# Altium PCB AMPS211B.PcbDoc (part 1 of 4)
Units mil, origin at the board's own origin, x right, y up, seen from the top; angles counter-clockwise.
Board outline 3600 x 2600 mil, 4 copper layers (Top Layer, GND, Power, Bottom Layer), stack 61.6 mil thick; 202 components, 101 nets, 561 pads, 317 vias.
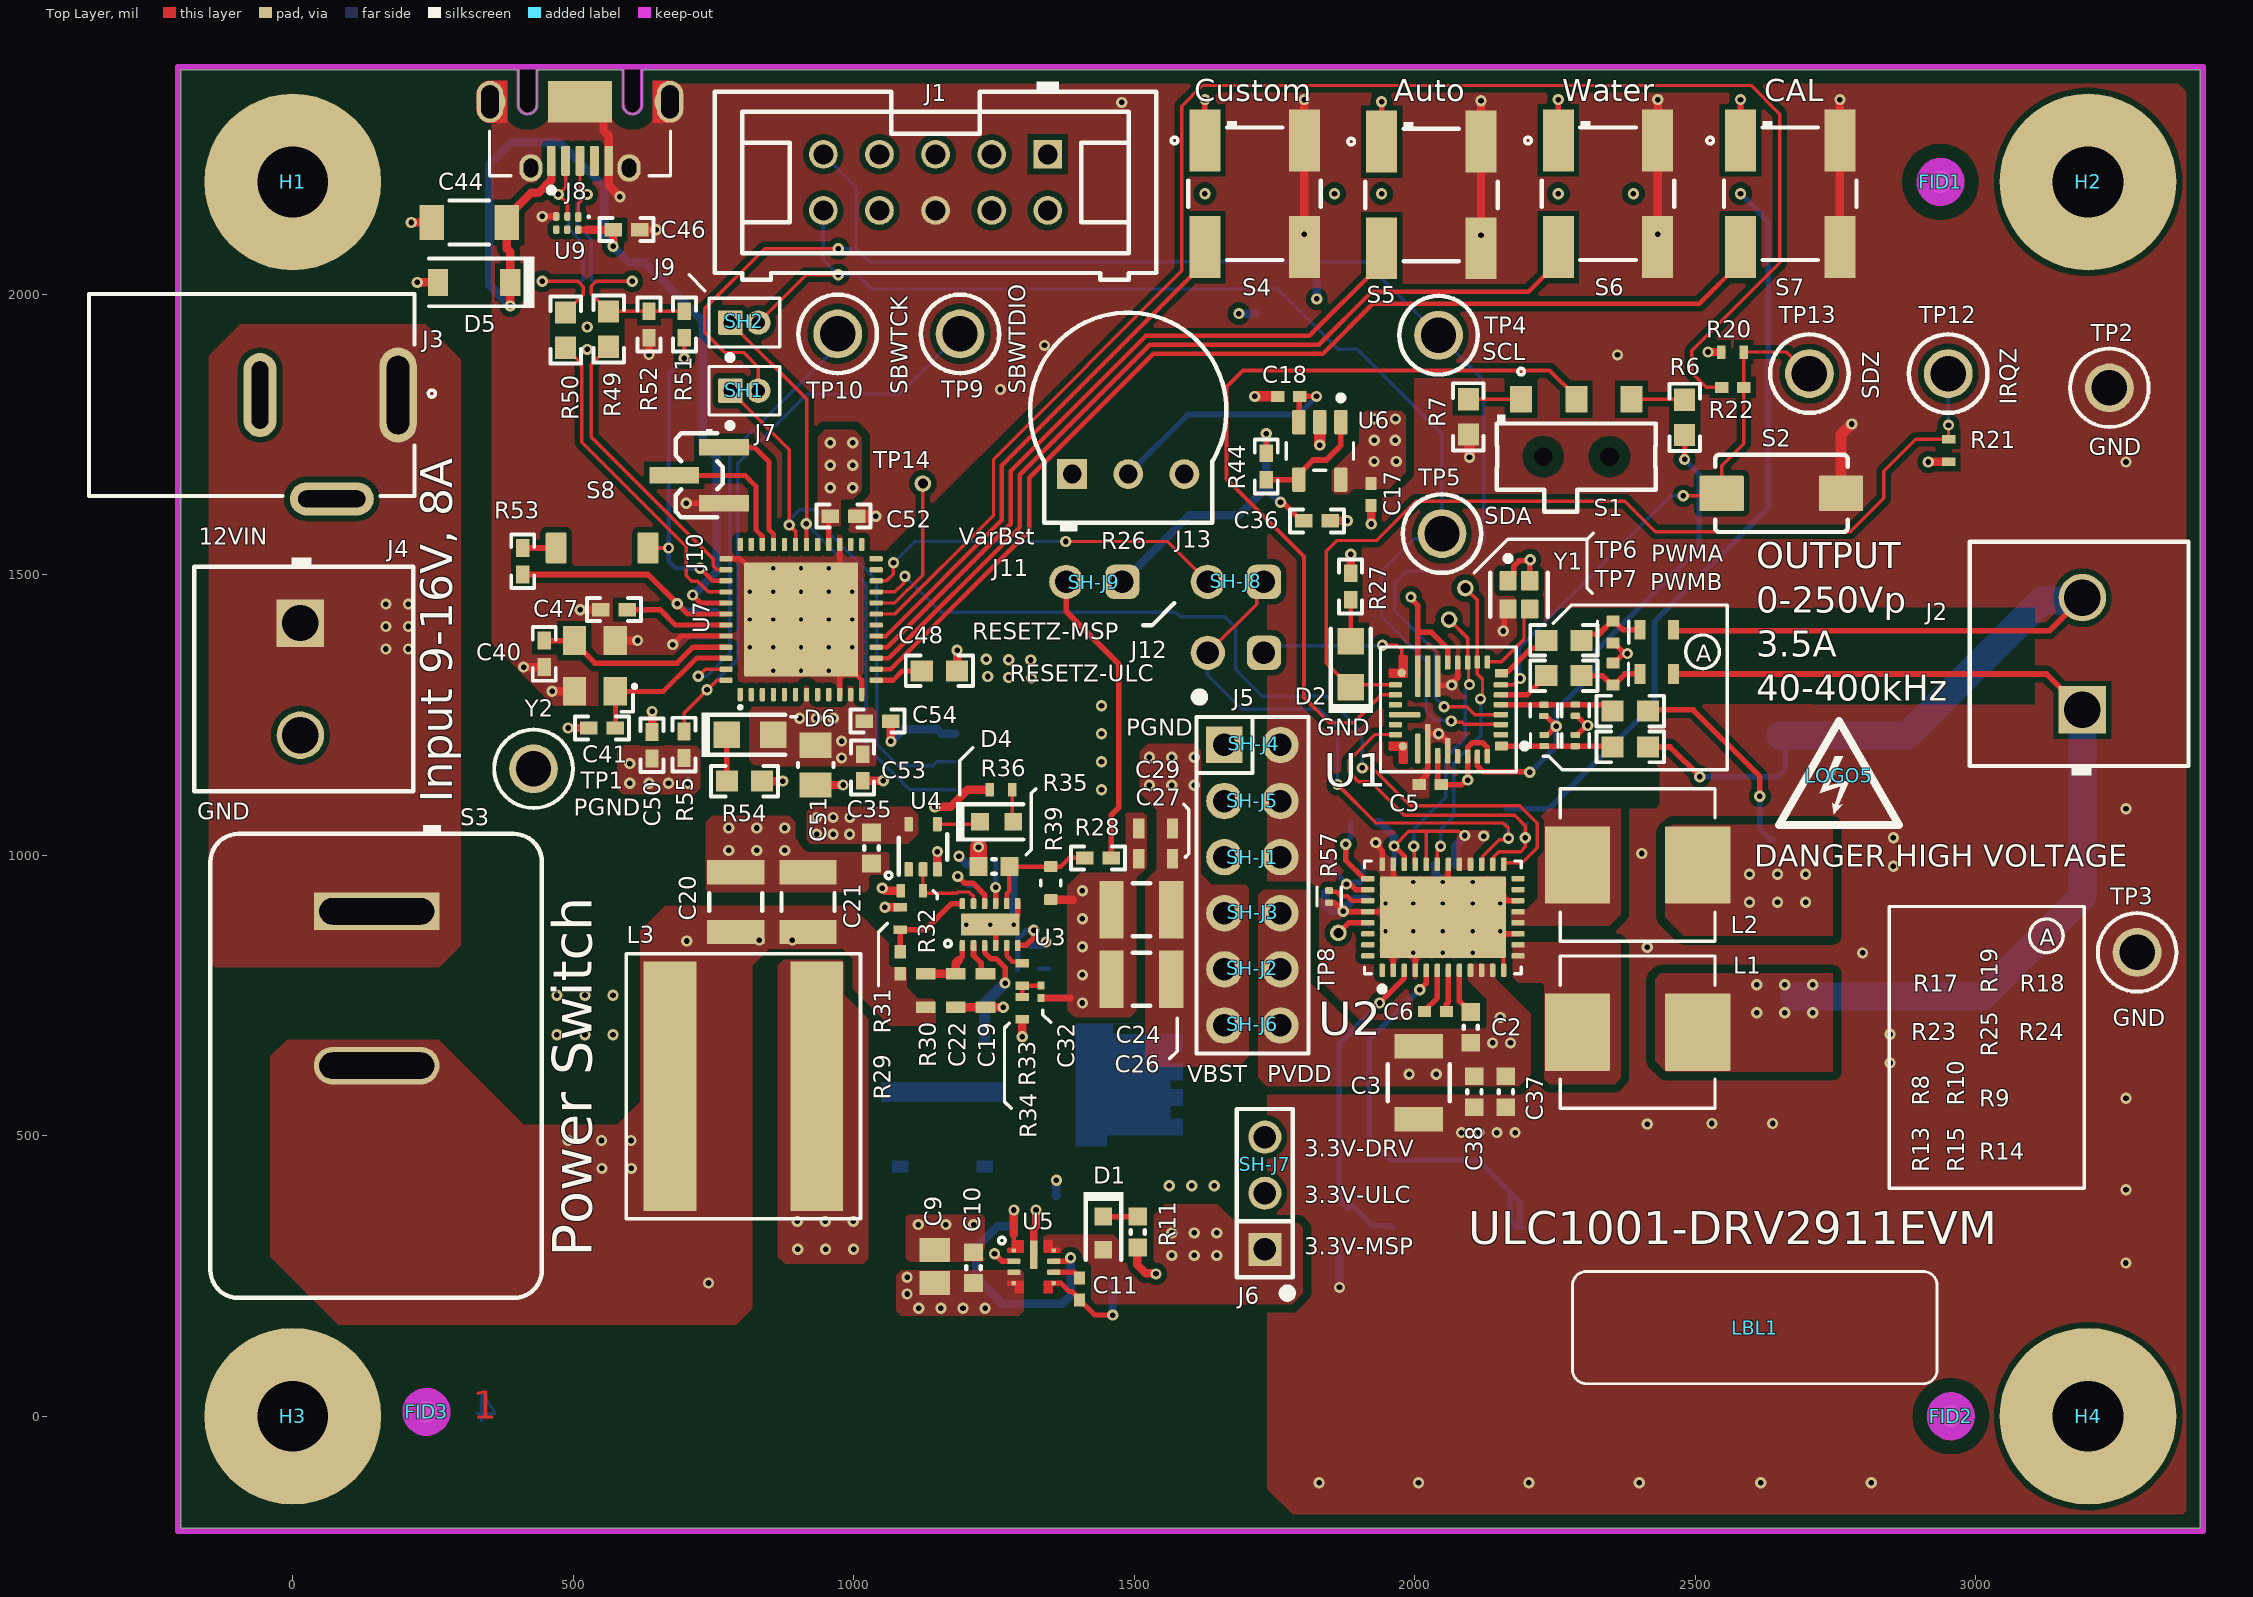
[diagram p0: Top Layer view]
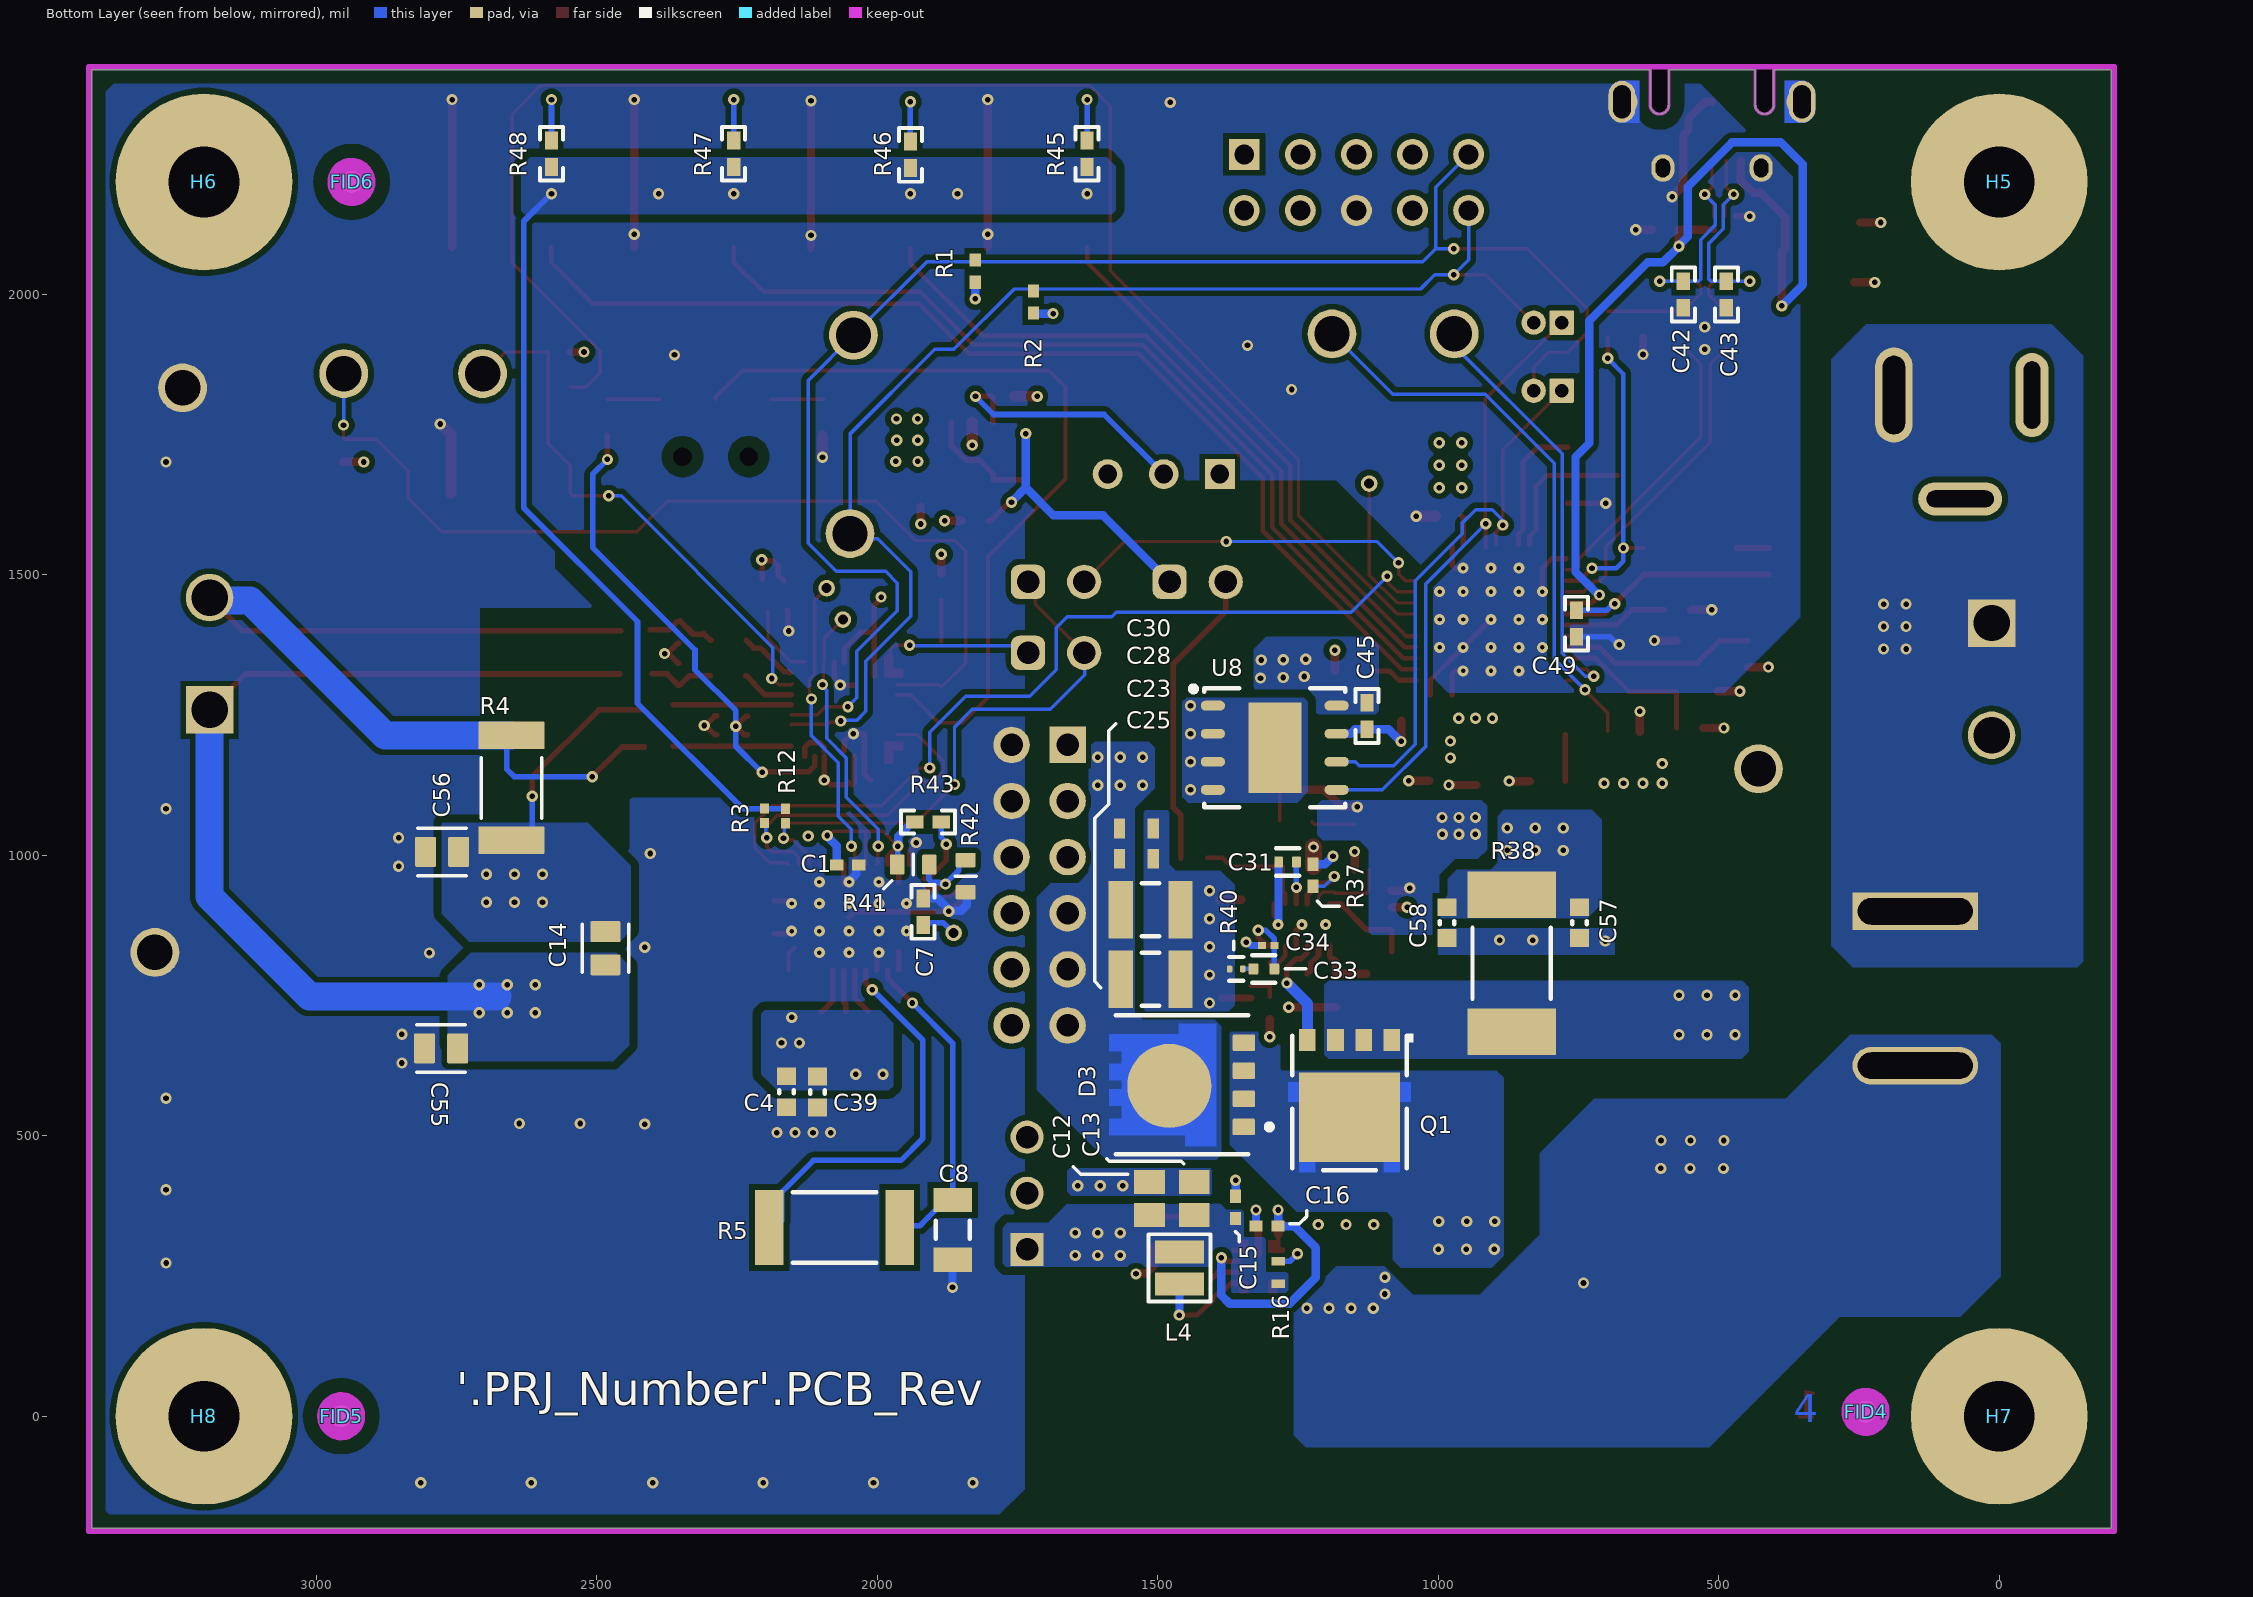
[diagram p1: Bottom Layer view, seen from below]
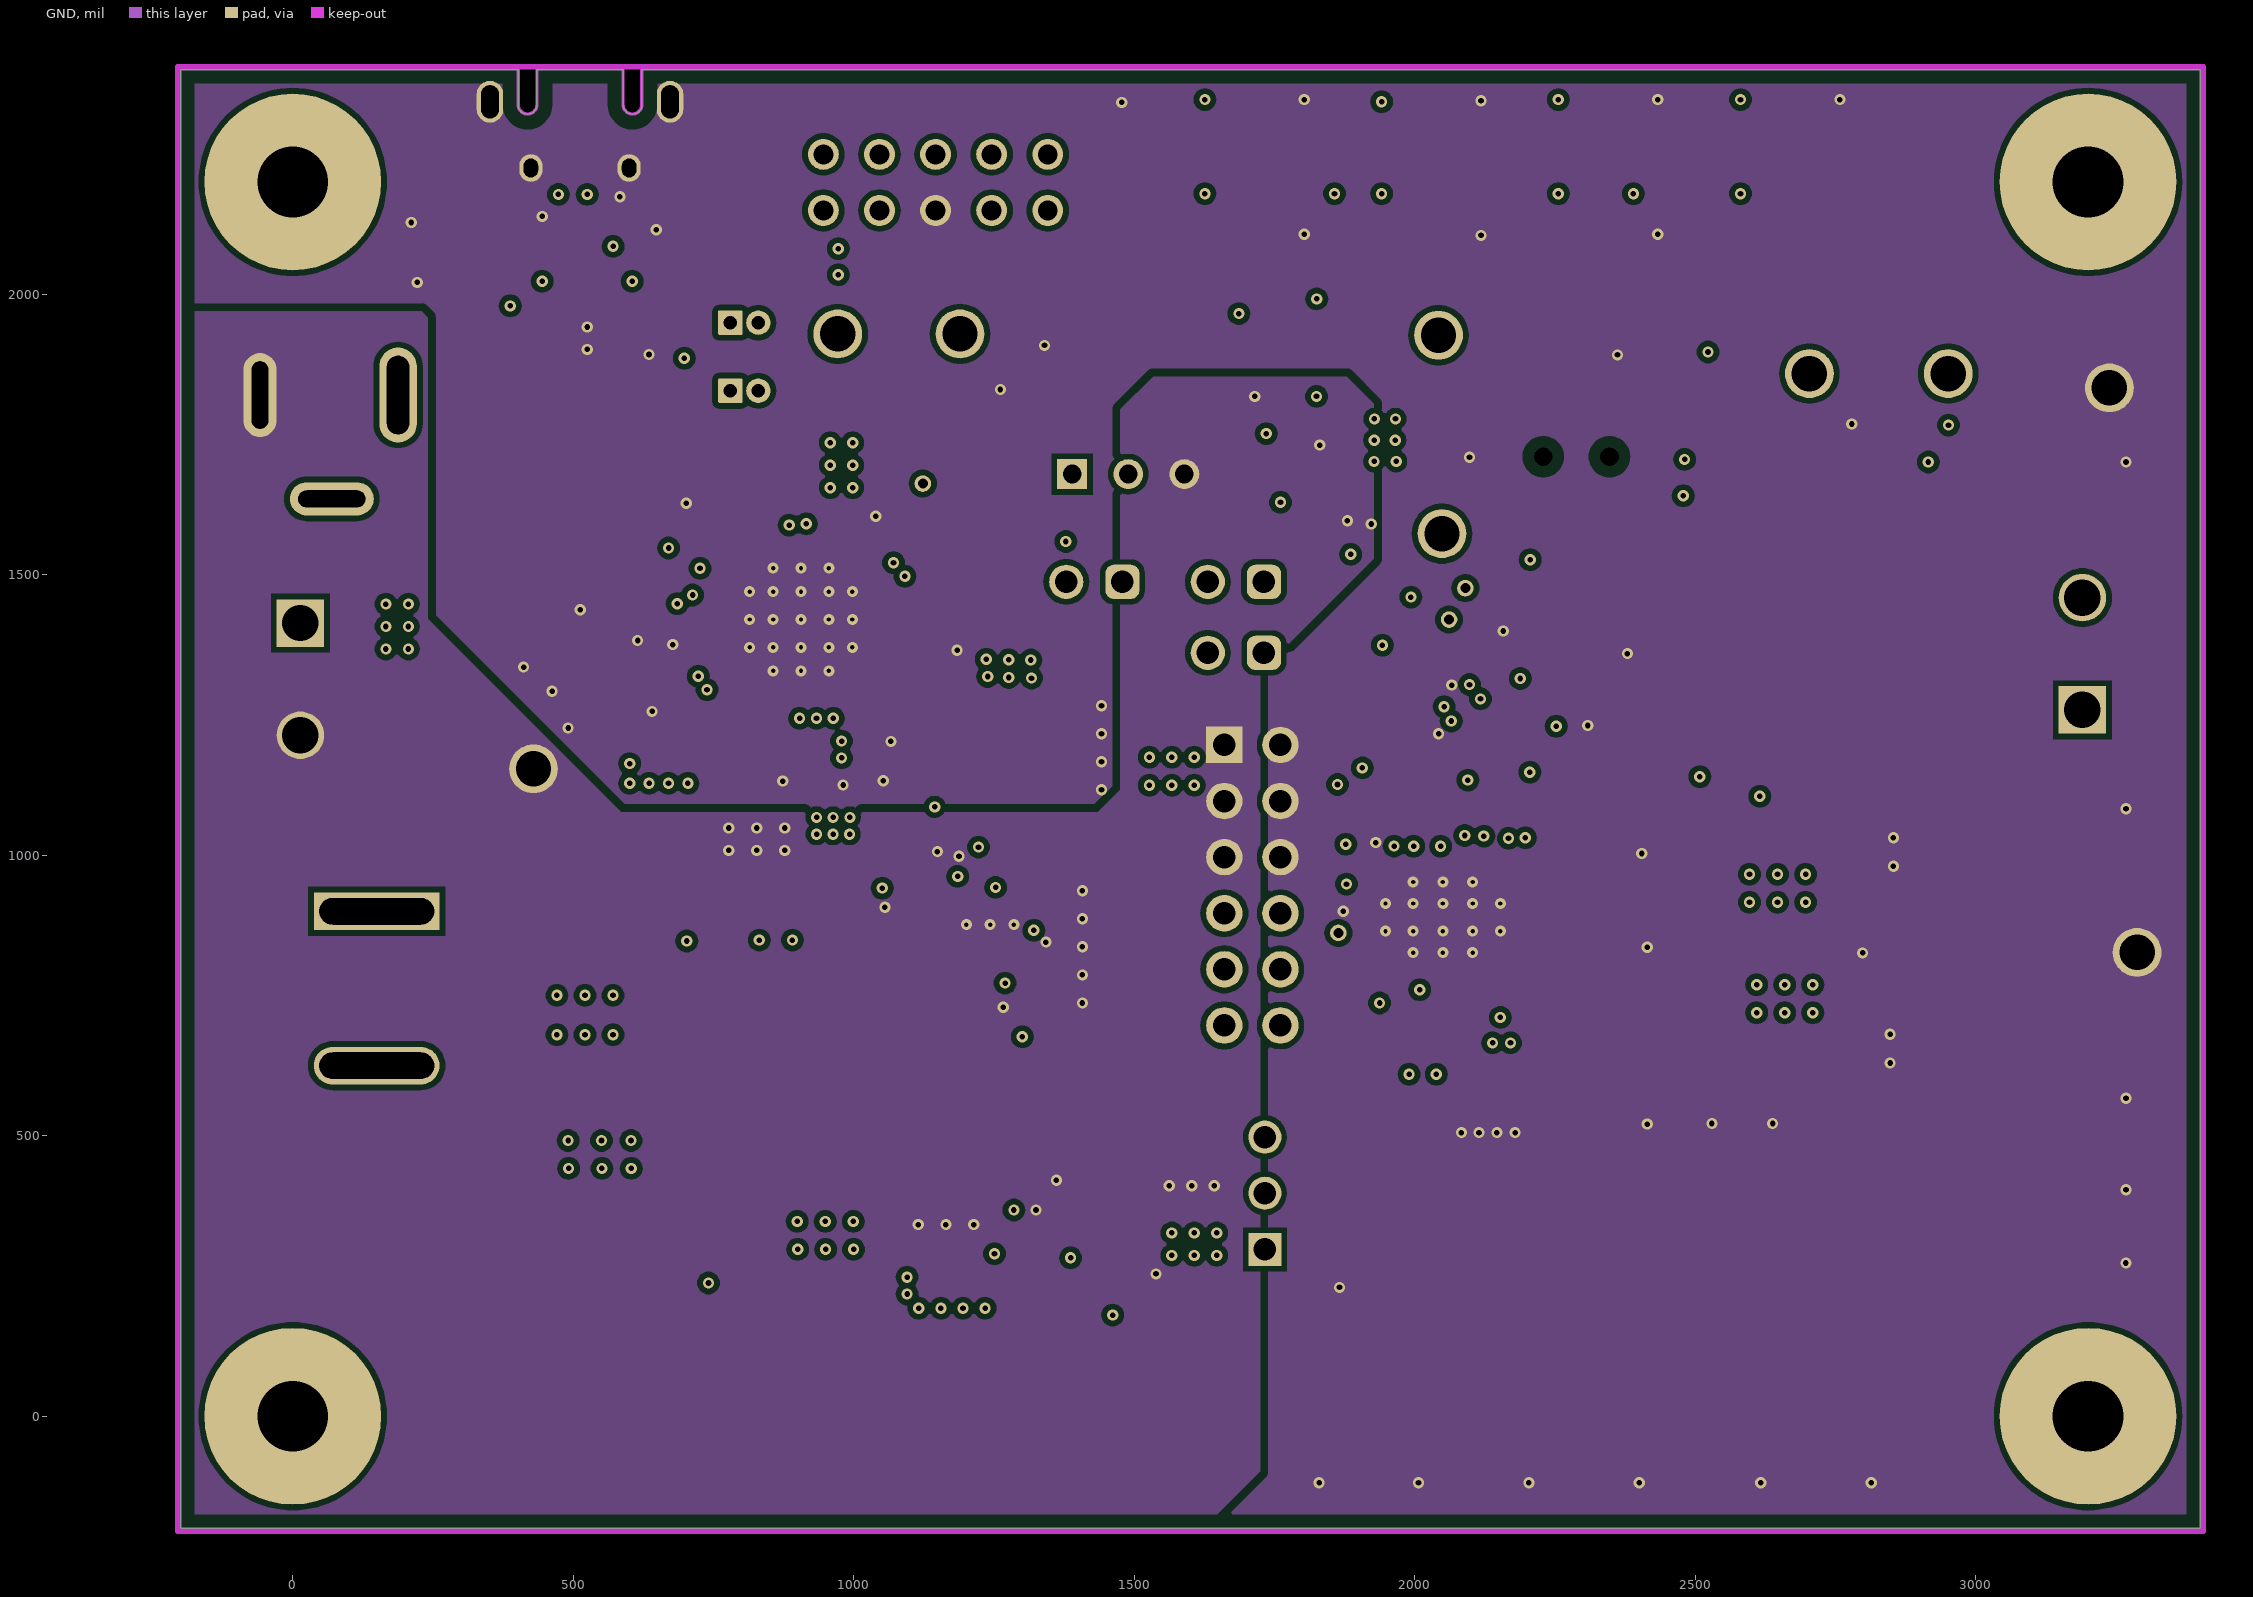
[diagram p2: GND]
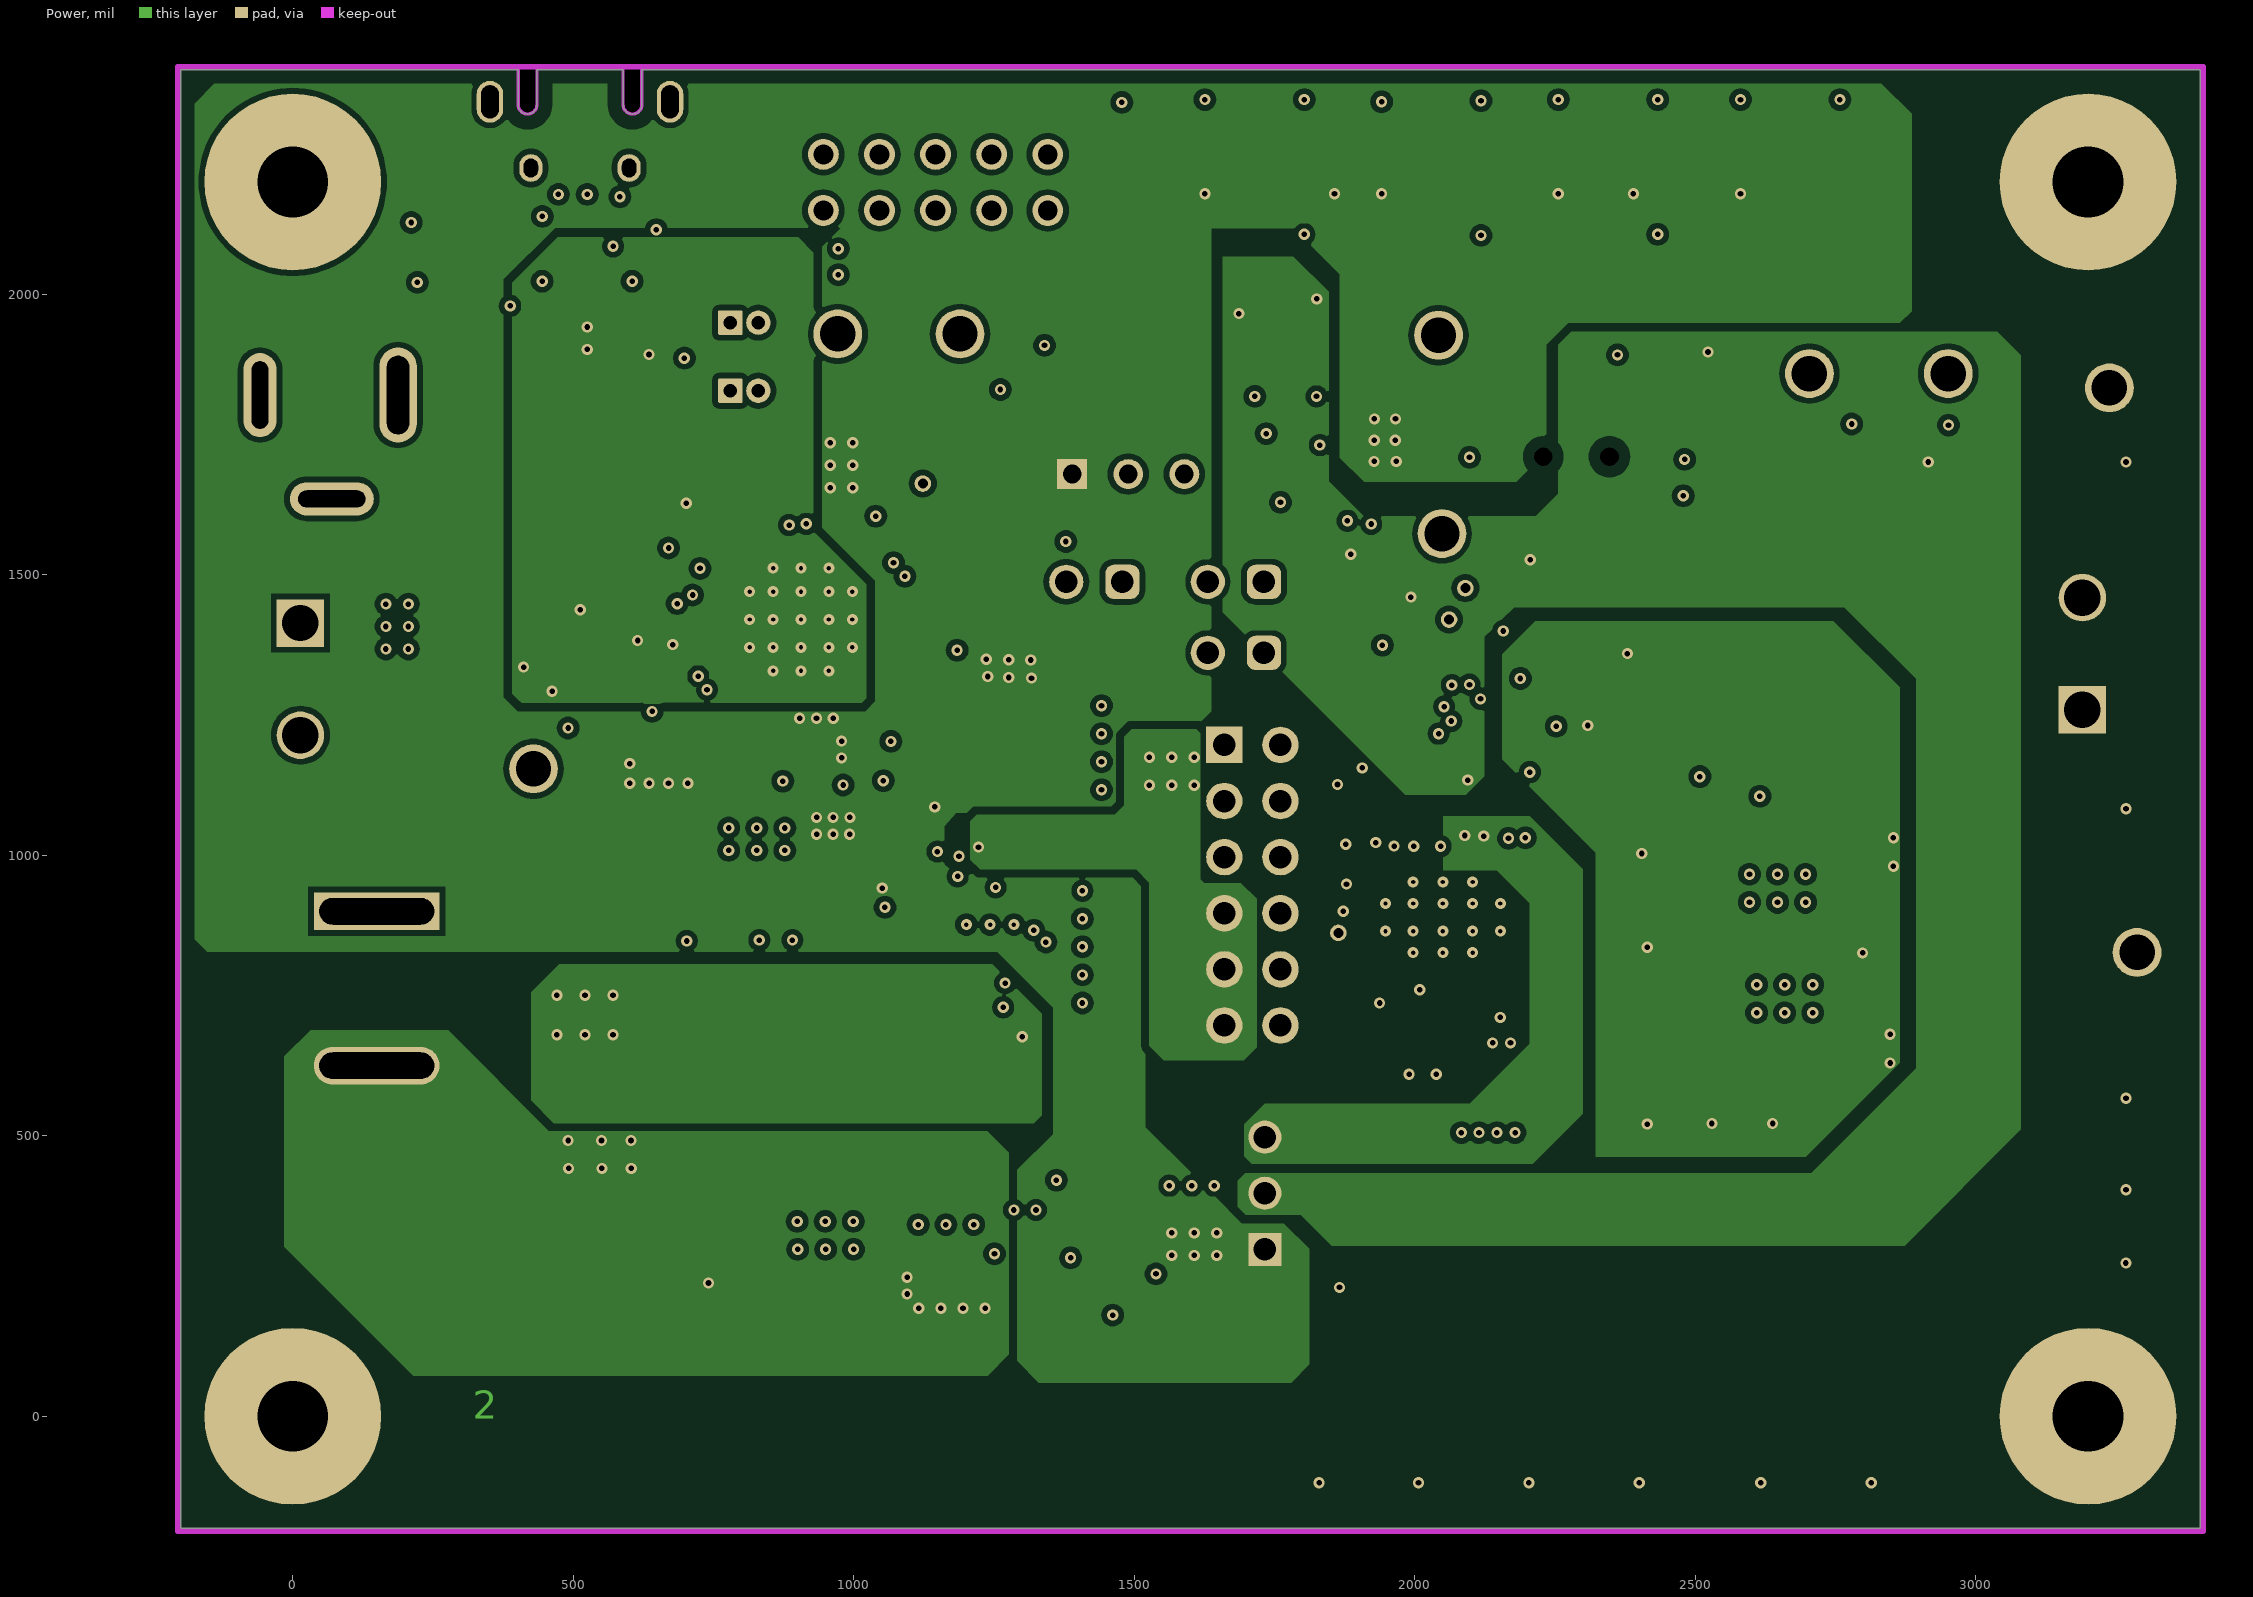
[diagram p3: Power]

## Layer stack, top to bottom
Top Solder: solder mask 0.4, Solder Resist, Dk 3.5
Top Layer: signal copper 1.4
Dielectric 4: prepreg 8, PP-006, Dk 4.1
GND: signal copper 1.4
Dielectric 2: core 40, FR-4 High Tg, Dk 4.2
Power: signal copper 1.4
Dielectric 3: prepreg 8, FR-4 High Tg, Dk 4.2
Bottom Layer: signal copper 1.4
Bottom Solder: solder mask 0.4, Solder Resist, Dk 3.5

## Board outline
-200,-200 -200,2400 401.77,2400 401.77,2337.99 ccw(c418.51,2337.74) 435.24,2337.99 435.24,2400 588.78,2400 588.78,2337.99 ccw(c605.51,2337.74) 622.24,2337.99 622.24,2400 3400,2400 3400,-200

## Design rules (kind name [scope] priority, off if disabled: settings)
AcuteAngle [All] p1: minimum=4.50000000000000E+0001 checktracksonly=FALSE
AssemblyTestPointUsage [All] p1: valid=2
Clearance Clearance_FiducialMark [IsKeepOut and InComponentClass('FiducialMark') vs IsPad and InComponentClass('FiducialMark')] p1: gap=0 ignorepadtopadclearanceinfootprint=FALSE
Clearance Clearance_J8 [HasFootprint('FP-0475901001_CONN_USB_7MM50_5MM90-MFG') and (ispad or IsRegion or IsArc) vs IsKeepOut] p2: gap=16.6 ignorepadtopadclearanceinfootprint=TRUE
Clearance Clearance_Keepouts [IsKeepOut] p3: gap=25 ignorepadtopadclearanceinfootprint=FALSE
Clearance Clearance_NPTH [IsThruPin and (padisplated=false)] p4: gap=20 ignorepadtopadclearanceinfootprint=FALSE
Clearance Clearance_Impedance [InNetClass('Impedance') and IsTrack vs (IsThruPin or IsVia) and (not InNet('GND'))] p5: gap=10.1 ignorepadtopadclearanceinfootprint=TRUE
Clearance "Clearance_Poly 2 Poly" [InPoly vs InPoly] p6: gap=15 ignorepadtopadclearanceinfootprint=FALSE
Clearance Clearance_Poly [InPolygon] p7: gap=10 ignorepadtopadclearanceinfootprint=FALSE
Clearance [All] p8: gap=7.87 ignorepadtopadclearanceinfootprint=TRUE
ComponentClearance ComponentClearance_1 [InComponent('SH-J1')or InComponent('SH-J2')or InComponent('SH-J3')or InComponent('SH-J4')or InComponent('SH-J5')or InComponent('SH-J6')or InComponent('SH-J7')or InComponent('SH1')or InComponent('SH2')or InComponent('SH-J8')or InComponent('SH-J9') vs InComponent('SH-J1')or InComponent('SH-J2')or InComponent('SH-J3')or InComponent('SH-J4')or InComponent('SH-J5')or InComponent('SH-J6')or InComponent('SH-J7')or InComponent('SH1')or InComponent('SH2')or InComponent('SH-J8')or InComponent('SH-J9')] p1: gap=0 collisioncheckmode=3 verticalgap=0 showdistances=FALSE
ComponentClearance "ComponentClearance_Header to shunt" [InComponent('J5')or InComponent('J6')or InComponent('J7')or InComponent('J9')or InComponent('J11')or InComponent('J12')or InComponent('J13') vs InComponent('SH-J1')or InComponent('SH-J2')or InComponent('SH-J3')or InComponent('SH-J4')or InComponent('SH-J5')or InComponent('SH-J6')or InComponent('SH-J7')or InComponent('SH1')or InComponent('SH2')or InComponent('SH-J8')or InComponent('SH-J9')] p2: gap=0 collisioncheckmode=3 verticalgap=0 showdistances=FALSE
ComponentClearance ComponentClearance_MountingHoles_FiducialMarks [InComponentClass('Mounting Holes') vs InComponentClass('FiducialMark')] p3: gap=50 collisioncheckmode=3 verticalgap=10 showdistances=FALSE
ComponentClearance ComponentClearance_Shunt [InComponentClass('Header') vs InComponentClass('Shunt')] p4: gap=0 collisioncheckmode=3 verticalgap=0 showdistances=FALSE
ComponentClearance ComponentClearance_Logo [InComponentClass('Logo')] p5: gap=30 collisioncheckmode=3 verticalgap=10 showdistances=FALSE
ComponentClearance ComponentClearance_ScrewToNut [HasFootprint('NY PMS 440 0025 PH') vs HasFootprint('Keystone_1902C')] p6: gap=5 collisioncheckmode=3 verticalgap=10 showdistances=FALSE
ComponentClearance ComponentClearance_MountingHoles [InComponentClass('Mounting Holes')] p7: gap=10 collisioncheckmode=3 verticalgap=100000 showdistances=FALSE
ComponentClearance ComponentClearance_SmallPassives [HasFootprint('0201*') or HasFootprint('0402*') or HasFootprint('0508') or HasFootprint('0603*') or HasFootprint('0612') or HasFootprint('0805*') or HasFootprint('0815*') or HasFootprint('0830*') or HasFootprint('1206*') or HasFootprint('1210*') or HasFootprint('1808*') or HasFootprint('1812*') or HasFootprint('1825*') or HasFootprint('2010*') or HasFootprint('2220*') or HasFootprint('2225*') or HasFootprint('2512*') or HasFootprint('2728*') or HasFootprint('3518*') vs HasFootprint('0201*') or HasFootprint('0402*') or HasFootprint('0508') or HasFootprint('0603*') or HasFootprint('0612') or HasFootprint('0805*') or HasFootprint('0815*') or HasFootprint('0830*') or HasFootprint('1206*') or HasFootprint('1210*') or HasFootprint('1808*') or HasFootprint('1812*') or HasFootprint('1825*') or HasFootprint('2010*') or HasFootprint('2220*') or HasFootprint('2225*') or HasFootprint('2512*') or HasFootprint('2728*') or HasFootprint('3518*')] p8: gap=14.96 collisioncheckmode=3 verticalgap=10 showdistances=FALSE
ComponentClearance ComponentClearance_THtoSMT [IsThruComponent vs IsSMTComponent] p9: gap=30 collisioncheckmode=3 verticalgap=30 showdistances=FALSE
ComponentClearance ComponentClearance_THtoTH [IsThruComponent vs IsThruComponent] p10: gap=20 collisioncheckmode=3 verticalgap=30 showdistances=FALSE
ComponentClearance [All] p11: gap=10 collisioncheckmode=3 verticalgap=10 showdistances=FALSE
DiffPairsRouting [All] p1: maxlimit=100 minlimit=10 mostfreqgap=10 toplayer_minwidth=15 toplayer_maxwidth=15 toplayer_prefwidth=15 midlayer1_minwidth=15 midlayer1_maxwidth=15 midlayer1_prefwidth=15 midlayer2_minwidth=15 midlayer2_maxwidth=15 midlayer2_prefwidth=15 bottomlayer_minwidth=15 bottomlayer_maxwidth=15 bottomlayer_prefwidth=15 maxuncoupledlength=1000
FabricationTestPointUsage TestPointUsage [All] p1: valid=2 allowmultiple=FALSE
FabricationTestpoint Testpoint [All] p1: side=3 testpointundercomponent=TRUE minsize=40 maxsize=100 preferedsize=60 minholesize=0 maxholesize=40 preferedholesize=32 testpointgrid=1 allowsidetop=TRUE allowsidebottom=TRUE usegrid=TRUE gridtolerance=0.01
FanoutControl Fanout_LCC [IsLCC] p1: bgadir=Out bgaviamode=Centered fanoutstyle=Auto fanoutdirection=Alternating viagrid=1 // Fanout_LCC (Default Rule)
FanoutControl Fanout_BGA [IsBGA] p2: bgadir=Out bgaviamode=Centered fanoutstyle=Auto fanoutdirection=Alternating viagrid=1 // Fanout_BGA (Default Rule)
FanoutControl Fanout_Default [All] p4: bgadir=Out bgaviamode=Centered fanoutstyle=Auto fanoutdirection=Alternating viagrid=1 // Fanout_Default (Default Rule)
FanoutControl Fanout_Small [(CompPinCount < 5)] p5: bgadir=Out bgaviamode=Centered fanoutstyle=Auto fanoutdirection=OutThenIn viagrid=1 // Fanout_Small (Default Rule)
HoleSize [All] p1: absolutevalues=TRUE maxlimit=251 minlimit=7.87 maxpercent=80.000 minpercent=20.000
MinimumAnnularRing MinimumAnnularRing_ThermalPadVias [IsVia and InAnyComponent] p1: minimumring=5.91
MinimumAnnularRing [All] p2: minimumring=5
MinimumSolderMaskSliver MinimumSolderMaskSliver_Logo [InComponentClass('Logo') vs InComponentClass('Logo')] p1: minsoldermaskwidth=0.7
MinimumSolderMaskSliver [All] p2: minsoldermaskwidth=3
PlaneConnect [All] p1: planeconnectstyle=Relief reliefexpansion=10 reliefentries=4 reliefconductorwidth=10 reliefairgap=10
PolygonConnect [All] p1: connectstyle=Direct reliefconductorwidth=10 reliefentries=4 polygonreliefangle="90 Angle" airgapwidth=10
RoutingVias ThermalPadVias [IsVia and InAnyComponent] p1: holewidth=7.87 width=19.68 viastyle="Through Hole" minholewidth=7.87 minwidth=19.68 maxholewidth=12.99 maxwidth=23.62
RoutingVias [All] p2: holewidth=16 width=34 viastyle="Through Hole" minholewidth=10 minwidth=20 maxholewidth=40 maxwidth=65
SilkToBoardRegionClearance [Not ((IsComment or IsDesignator) And (Hide <> 'False')) and not InRegion(1000,500,4000,800)] p1:
SilkToSilkClearance SilkToSilkClearance_Pb-FreeLogo [(HasFootprint('Pb-Free_Overlay_Medium') OR HasFootprint('Pb-Free_Overlay_Small')) vs (HasFootprint('Pb-Free_Overlay_Medium') OR HasFootprint('Pb-Free_Overlay_Small'))] p1: silktosilkclearance=0
SilkToSilkClearance [All] p2: silktosilkclearance=3.94
SilkToSolderMaskClearance SilkToComponentPadClearance [(IsPad or IsFill or IsRegion) and InAnycomponent] p1: minsilkscreentomaskgap=5 clearancetoexposedcopper=TRUE
SilkToSolderMaskClearance "Silk to Solder Mask Opening" [All] p2: minsilkscreentomaskgap=3.94 clearancetoexposedcopper=FALSE
SolderMaskExpansion SolderMaskExpansion_NPTH [IsThruPin and (PadIsPlated='False')] p1: expansion=5 istentingtop=FALSE soldermaskfromhole=TRUE
SolderMaskExpansion SolderMaskExpansion_PTH [IsThruPin] p2: expansion=2.5 istentingtop=FALSE
SolderMaskExpansion [All] p3: expansion=0 istentingtop=FALSE
UnRoutedNet [All] p1: checkbadconnections=TRUE
Width Width_IMP [InNetClass('Impedance')] p1: maxlimit=10 minlimit=6.2 preferedwidth=10 toplayer_maxwidth=6.2 toplayer_prefwidth=6.2 midlayer1_minwidth=10 midlayer2_minwidth=10 bottomlayer_maxwidth=6.2 bottomlayer_prefwidth=6.2 minimp=50.000000 maximp=50.000000 favimp=50.000000
Width [All] p2: maxlimit=100 minlimit=6 preferedwidth=10
14 further rules are at their usual default settings.

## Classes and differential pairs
component class AMPS211B_DUT: C1 C2 C3 C4 C5 C6 C7 C8 C14 C37 C38 C39 C55 C56 D2 J1 J2 J12 J13 L1 L2 R1 R2 R3 R4 R5 R6 R7 R8 R9 R10 R12 R13 R14 R15 R17 R18 R19 R20 R21 R22 R23 R24 R25 R27 R41 R42 R43 R57 S1 S2 TP4 TP5 TP6 TP7 TP8 TP12 TP13 U1 U2 Y1
component class Header: J5 J6 J10 J11 J12 J13
net class Impedance: D+ D- DM DP INCLK PWMA PWMB SBWTCK SBWTDIO SCL SCL_MSP SDA SDA_MSP
net class Power: 3.3V-MSP 12VIN 12VIN_SW DRAIN OUT_A OUT_B OUT_XA OUT_XB PVDD SOURCE VBST
component class AMPS211B_PwrMod_Regs: C9 C10 C11 C12 C13 C15 C16 C17 C18 C19 C20 C21 C22 C23 C24 C25 C26 C27 C28 C29 C30 C31 C32 C33 C34 C35 C36 C57 C58 D1 D3 D4 J3 J4 J5 J6 J11 L3 L4 Q1 R11 R16 R26 R28 R29 R30 R31 R32 R33 R34 R35 R36 R37 R38 R39 R40 R44 S3 U3 U4 U5 U6
component class AMPS211B_MSP430: C40 C41 C42 C43 C44 C45 C46 C47 C48 C49 C50 C51 C52 C53 C54 D5 D6 J7 J8 J9 J10 R45 R46 R47 R48 R49 R50 R51 R52 R53 R54 R55 S4 S5 S6 S7 S8 SH1 SH2 TP9 TP10 TP14 U7 U8 U9 Y2
component class "Mounting Holes": H1 H2 H3 H4
component class AMPS211B_Hardware: FID1 FID2 FID3 FID4 FID5 FID6 H1 H2 H3 H4 H5 H6 H7 H8 LBL1 LOGO5 SH-J1 SH-J2 SH-J3 SH-J4 SH-J5 SH-J6 SH-J7 SH-J8 SH-J9 TP1 TP2 TP3 ZZ1 ZZ2 ZZ3 ZZ4 ZZ5
component class FiducialMark: FID1 FID2 FID3 FID4 FID5 FID6
component class AssemblyNote: ZZ1 ZZ2 ZZ3 ZZ4 ZZ5
component class Label: LBL1

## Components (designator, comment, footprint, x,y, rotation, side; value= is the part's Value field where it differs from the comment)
C1 "EMK105BJ105KVHF" 0402L 2052.5,982.75 r180 bottom locked value=1uF
C2 "UMK107AB7105KA-T" 0603L 2099.7,692.99 r90 top value=1uF
C3 "CGA6P1X7R1N106M250AC" 1210_280 2007.24,594.45 r270 top value=10uF
C4 "GRM188R72A104KA35J" 0603L 2161.85,578.31 r270 bottom value=0.1uF
C5 "EMK105BJ105KVHF" 0402L 2027.56,1125.98 r180 top value=1uF
C6 "C1005X7R1H473K050BB" 0402L 2036.85,721.5 r0 top value=0.047uF
C7 "GRM155R70J104KA01D" 0402 1918.07,899.11 r90 bottom locked value=0.1uF
C8 "GRM31CR71A226KE15L" 1206_180L 1865.43,332.3 r270 bottom value=22uF
C9 "CGA4J3X7R1H225K125AB" 0805L 1144.28,266.87 r90 top value=2.2uF
C10 "CGA3E2X7R1H104K080AA" 0603L 1213.18,264.9 r90 top value=0.1uF
C11 "CGA2B3X7R1H104K050BD" 0402L 1402.58,226.87 r270 top value=0.1uF
C12 "GCJ21BR71A106KE01L" 0805L 1514.51,388.06 r90 bottom locked value=10uF
C13 "GCJ21BR71A106KE01L" 0805L 1434.86,388.06 r90 bottom locked value=10uF
C14 "C2012X7T2W473K125AA" FP-C0805C472KBRACAUTO_0805-MFG 2484.39,834.13 r270 bottom locked value=47nF
C15 "GCM155R71C104JA55D" 0402L 1361.16,372.22 r90 bottom locked value=0.1uF
C16 "EMK105BJ105KVHF" 0402L 1305.06,338.76 r0 bottom locked value=1uF
C17 "GCM155R71C104JA55D" 0402L 1922.19,1642.82 r270 top value=0.1uF
C18 "GCM155R71C104JA55D" 0402L 1775.36,1817.76 r180 top value=0.1uF
C19 "GCM188R71E105KA64D" 0603S 1234.87,758.83 r270 top value=1uF
C20 "CL32B226KAJNFNE" 1210_270L 789.29,916.3 r90 top value=22uF
C21 "CL32B226KAJNFNE" 1210_270L 918.44,916.3 r90 top value=22uF
C22 "GCM188R71E105KA64D" 0603S 1181.72,758.83 r270 top value=1uF
C23 "CL32B106KBJNNWE" 1210_270L 1512.62,902.9 r180 bottom locked value=10uF
C24 "CL32B106KBJNNWE" 1210_270L 1512.62,902.9 r180 top value=10uF
C25 "CL32B106KBJNNWE" 1210_270L 1512.62,778.9 r180 bottom locked value=10uF
C26 "CL32B106KBJNNWE" 1210_270L 1512.62,778.9 r180 top value=10uF
C27 "GRM188R72A104KA35J" 0603S 1538.05,993.48 r180 top value=0.1uF
C28 "GRM188R72A104KA35J" 0603S 1538.05,993.48 r180 bottom locked value=0.1uF
C29 "CGA3E2X7R2A103K080AA" 0603S 1538.05,1047.52 r180 top value=0.01uF
C30 "CGA3E2X7R2A103K080AA" 0603S 1538.05,1047.52 r180 bottom locked value=0.01uF
C31 "CGA2B1X7R1A154M050BC" FP-CGA2B1X7R1A154M050BC_0402-MFG 1268.53,987.91 r0 bottom locked
C32 "CGA1A2X7R1E102K030BA" 0201_033L 1333.79,756.31 r270 top value=1000pF
C33 "LMF105B7473KVHF" FP-LMF105B7473KVHF_0402-MFG 1310.85,797.23 r180 bottom locked
C34 "GRM033R71A182KA01D" 0201L 1303.17,838.83 r0 bottom locked value=1800pF
C35 "CGA3E2X7R1H104K080AA" 0603L 1031.59,1012.8 r270 top value=0.1uF
C36 "CL05B103KA5NNNC" 0402 1825.47,1595.96 r0 top value=0.01uF
C37 "GRM188R72A104KA35J" 0603L 2162.17,578.22 r270 top value=0.1uF
C38 "GRM188R72A104KA35J" 0603L 2106.06,578.22 r270 top value=0.1uF
C39 "GRM188R72A104KA35J" 0603L 2106.52,577.94 r270 bottom value=0.1uF
C40 "CL05C180JB5NNNC" 0402 448.24,1358.95 r90 top value=18pF
C41 "CL05C180JB5NNNC" 0402 551.3,1226.63 r0 top value=18pF
C42 "CGA2B2C0G1H100D050BA" 0402 563.19,1999.33 r270 bottom locked value=10pF
C43 "CGA2B2C0G1H100D050BA" 0402 486.42,1999.33 r270 bottom locked value=10pF
C44 "GCM31CR71E475KA55L" 1206_180 314.77,2127.7 r180 top value=4.7uF
C45 "EMK105B7104KV-F" 0402 1126.9,1248.17 r270 bottom locked value=0.1uF
C46 "EMK105B7104KV-F" 0402 594.66,2114.91 r0 top value=0.1uF
C47 "LMK105B7224KVHF" 0402 572.76,1437.6 r180 top locked value=0.22uF
C48 "C0603C474K8RACTU" 0603 1152.65,1328.51 r0 top locked value=0.47uF
C49 "LMK105B7224KVHF" 0402 753.58,1412.67 r270 bottom value=0.22uF
C50 "C1005NP01H102J050BA" 0402 640.51,1195.92 r90 top value=1000pF
C51 "885012107014" 0805_150 932.17,1160.58 r270 top value=10uF
C52 "EMK105B7104KV-F" 0402 981.74,1604.29 r0 top value=0.1uF
C53 "EMK105B7104KV-F" 0402 1015.85,1156.49 r270 top locked value=0.1uF
C54 "EMK105B7104KV-F" 0402 1042.48,1238.83 r0 top locked value=0.1uF
C55 "DNP" FP-C0805C822JAGACAUTO_0805-MFG 2777.22,655.6 r0 bottom value=8.2nF
C56 "DNP" FP-C0805C822JAGACAUTO_0805-MFG 2775.43,1005.93 r180 bottom value=8.2nF
C57 "CGA3E2X7R1H104K080AA" 0603L 748.03,879.92 r90 bottom value=0.1uF
C58 "CGA3E2X7R1H104K080AA" 0603L 984.25,879.92 r90 bottom value=0.1uF
D1 "VREG" LTST-C193_Green 1444.91,326.43 r90 top value=Green
D2 "LTST-C170KRKT" LED_LTST-C170_Red 1885.73,1340.41 r270 top value=Red
D3 "V30K45-01HM3/H" FP-V30K45-01HM3-H_FlatPAK5x6-MFG 1456.62,590.7 r90 bottom locked
D4 "VBST-PGOOD" LTST-C193_Blue 1254.6,1059.42 r180 top value=Blue
D5 "5V-USB" SOD-123 323.23,2020.98 r180 top value=5.6V
D6 "3.3V-MSP" LED_LTST-C171 815.03,1214.68 r180 top value=Green
FID1 "Fiducial" Fiducial10-20 2936.9,2200 r0 top
FID2 "Fiducial" Fiducial10-20 2955.4,-0.01 r0 top
FID3 "Fiducial" Fiducial10-20 238.2,7.81 r0 top
FID4 "Fiducial" Fiducial10-20 238.2,7.81 r180 bottom locked
FID5 "Fiducial" Fiducial10-20 2955.4,-0.01 r180 bottom locked
FID6 "Fiducial" Fiducial10-20 2936.9,2200 r180 bottom locked
H1 "NY PMS 440 0025 PH" "NY PMS 440 0025 PH" 0,2200 r0 top locked
H2 "NY PMS 440 0025 PH" "NY PMS 440 0025 PH" 3200,2200 r0 top locked
H3 "NY PMS 440 0025 PH" "NY PMS 440 0025 PH" 0,0 r0 top locked
H4 "NY PMS 440 0025 PH" "NY PMS 440 0025 PH" 3200,0 r0 top locked
H5 "1902C" Keystone_1902C 0,2200 r180 bottom locked
H6 "1902C" Keystone_1902C 3200,2200 r180 bottom locked
H7 "1902C" Keystone_1902C 0,0 r180 bottom locked
H8 "1902C" Keystone_1902C 3200,0 r180 bottom locked
J1 "XG4C-1031" OMRON_XG4C-1031 1145.8,2199.19 r270 top
J2 "OUT" Molex_039544-3002 3190,1359 r90 top
J3 "VIN" CONN_RAPC712X -353.28,1820.16 r180 top locked
J4 "VIN" Molex_039544-3002 13.65,1313.83 r270 top
J5 "PEC06DAAN" CONN_PEC06DAAN 1710.52,946.5 r270 top
J6 "PEC03SAAN" CONN_PEC03SAAN 1732.73,397.45 r90 top
J7 "M50-3530242" FP-M50-3530242_HDR2-MFG 804.84,1827.83 r0 top
J8 "0475901001" FP-0475901001_CONN_USB_7MM50_5MM90-MFG 512.01,2335.04 r180 top locked
J9 "M50-3530242" FP-M50-3530242_HDR2-MFG 804.84,1949.13 r0 top
J10 "GRPB031VWTC-RC" Sullins_GRPB031VWTC 724.5,1677.14 r270 top
J11 "VariableBoost" Samtec_TSW-102-07-T-S 1428.74,1487.2 r180 top
J12 "TSW-102-07-T-S" Samtec_TSW-102-07-T-S 1681.1,1360.63 r180 top
J13 "TSW-102-07-T-S" Samtec_TSW-102-07-T-S 1681.1,1487.2 r180 top
L1 "SPM6545VT-220M-D" FP-SRP7050TA-220M_SMT2_7MM3_6MM6-MFG 2397.11,684.53 r0 top value=22uH
L2 "SPM6545VT-220M-D" FP-SRP7050TA-220M_SMT2_7MM3_6MM6-MFG 2397.11,982.55 r0 top value=22uH
L3 "XAL1010-682MEB" XAL1010 803.28,588.23 r0 top value=6.8uH
L4 "XPL2010-103MLB" XPL2010 1461.11,264.29 r90 bottom locked value=10uH
LBL1 "THT-14-423-10" Label_650x200 2606,158 r0 top
LOGO5 "DANGER HIGH VOLTAGE" IEC_HighVoltage_Small 2755.91,1141.73 r0 top
Q1 "NTMFS5C670NLT1G" SO-8FL 1158.09,560.22 r270 bottom locked value=60V
R1 "CRCW04022K20JNED" 0402L 1825.17,2041 r270 bottom value=2.2k
R2 "CRCW04022K20JNED" 0402L 1721.62,1985.88 r270 bottom value=2.2k
R3 "RC0201FR-075K1L" 0201 2200.79,1070.08 r90 bottom value=5.10k
R4 "VMP-1R00-1.0-U" FP-VMP-1R00-1.0-U_2010-MFG 2652,1120 r90 bottom value=1
R5 "CRCW251222R0JNEGHP" 2512 2075.99,336.27 r180 bottom value=22
R6 "RC0603JR-070RL" 0603 2480.93,1780.29 r90 top value=0
R7 "RC0603JR-070RL" 0603 2095.56,1781.23 r90 top value=0
R8 "TNPW02016K04BEED" FP-TNPW02016K04BEED_0201-MFG 2230.11,1258.17 r270 top value=6.04k
R9 "RT0603BRD07422KL" 0603 2383.86,1256.89 r0 top value=422k
R10 "TNPW02012K00BEED" FP-TNPW02012K00BEED_0201-MFG 2286.33,1258.43 r90 top value=2k
R11 "CRCW0603499RFKEAC" 0603L 1506.16,328.4 r90 top value=499
R12 "RC0201FR-075K1L" 0201 2163.39,1069.88 r90 bottom value=5.10k
R13 "TNPW02016K04BEED" FP-TNPW02016K04BEED_0201-MFG 2230.66,1204.39 r90 top value=6.04k
R14 "RT0603BRD07422KL" 0603 2383.86,1192.91 r0 top value=422k
R15 "TNPW02012K00BEED" FP-TNPW02012K00BEED_0201-MFG 2286.33,1204.36 r270 top value=2k
R16 "RC0402FR-0710KL" 0402S 1285.37,256.24 r270 bottom locked value=10.0k
R17 "RT0603BRD07294KL" 0603 2265.75,1382.87 r0 top value=294k
R18 "MCT0603MD1304BP500" 0603S 2431.13,1401.57 r0 top value=1.3M
R19 "RT0402BRD076K34L" FP-RT0402BRD076K34L_0402-MFG 2353.35,1397.64 r90 top value=6.34k
R20 "RC0402FR-0710KL" 0402S 2566.4,1896.85 r0 top value=10.0k
R21 "RC0402FR-0710KL" 0402S 2951.35,1721.11 r90 top value=10.0k
R22 "ERJ-2GE0R00X" 0402L 2566.71,1833.86 r180 top value=0
R23 "RT0603BRD07294KL" 0603 2265.75,1319.88 r0 top value=294k
R24 "MCT0603MD1304BP500" 0603S 2431.13,1322.83 r0 top value=1.3M
R25 "RT0402BRD076K34L" FP-RT0402BRD076K34L_0402-MFG 2353.35,1322.83 r270 top value=6.34k
R26 "3352T-1-103LF" Bourns_3352T 1489.23,1679.28 r0 top value=10kΩ
R27 "CRCW0402499RFKED" 0402 1885.73,1478.85 r270 top value=499
R28 "CRCW04029K76FKED" 0402 1435.06,995.01 r0 top value=9.76k
R29 "ERJ-2RKF1003X" 0402L 1082.84,808.31 r270 top value=100k
R30 "CRCW060310R0FKEA" 0603S 1128.33,758.83 r270 top value=10.0
R31 "CRCW040220K5FKED" 0402S 1082.84,887.05 r270 top value=20.5k
R32 "RC0402FR-0710KL" 0402S 1103.43,936.27 r0 top value=10.0k
R33 "ERJ-2RKF1000X" 0402S 1300.46,787.33 r270 top value=665
R34 "ERJ-2RKF1000X" 0402S 1300.46,727.29 r270 top value=100
R35 "CRCW0603100KFKEA" 0603L 1249.9,979.81 r180 top value=100k
R36 "CRCW0402150RFKED" 0402S 1262.15,1116.55 r0 top value=150
R37 "CRCW040248K7FKED" 0402L 1223.34,964.1 r270 bottom locked value=48.7k
R38 "CRE2512-FZ-R005E-3" CRE2512-R5_R9 869.02,807.35 r270 bottom value=0.005
R39 "RK73H1JTTD3481F" FP-RK73H1JTTD3481F_0603-MFG 1351.2,950.28 r90 top value=3.48k
R40 "ERJ-1GNF2261C" FP-ERJ-1GNF2261C_0201-MFG 1360.17,797.23 r180 bottom locked
R41 "" FP-ERJ-H3G0R00V_0603-MFG 1935.63,983.27 r0 bottom value=0
R42 "DNP" FP-ERJ-H3G0R00V_0603-MFG 1842.33,962.7 r90 bottom value=0
R43 "CRCW040247K0JNED" 0402 1909.45,1059.06 r0 bottom value=47k
R44 "CRCW04025R11FKED" 0402 1735.22,1693.03 r270 top value=5.11
R45 "CRCW040210K0JNED" 0402 1625.85,2250.3 r270 bottom locked value=10k
R46 "CRCW040210K0JNED" 0402 1940.82,2248.33 r270 bottom locked value=10k
R47 "CRCW040210K0JNED" 0402 2255.78,2250.3 r270 bottom locked value=10k
R48 "CRCW040210K0JNED" 0402 2580.58,2250.3 r270 bottom locked value=10k
R49 "RC0603FR-0727R4L" 0603 563.19,1937.79 r90 top value=27.4
R50 "RC0603FR-0727R4L" 0603 486.42,1936.03 r90 top value=27.4
R51 "CRCW04021K40FKED" 0402 698.01,1945.67 r90 top value=1.40k
R52 "CRCW04021M00JNED" 0402 635.04,1945.67 r90 top value=1.0Meg
R53 "CRCW0402100RFKED" 0402 409.96,1523.91 r270 top value=100
R54 "CRCW0603499RFKEAC" 0603 805.19,1132 r180 top value=499
R55 "CRCW040247K0JNED" 0402 697.42,1196.96 r270 top value=47k
R57 "" FP-HCJ0201ZT0R00_0201-MFG 1847.24,926.18 r90 top value=0
S1 "I2C Sel" SW_AYZ0102AGRLC 2287.91,1710.37 r0 top
S2 "Shutdown" SW_EVQ5PN04K 2653.33,1644.88 r180 top
S3 "SRB22A2FBBNN" SW_SRB22A2FBBNN 149.65,624.86 r270 top
S4 "PB4" SW_TL3301_J 1714.44,2178.94 r0 top
S5 "PB3" SW_TL3301_J 2029.4,2176.97 r0 top
S6 "PB2" SW_TL3301_J 2344.36,2178.94 r0 top
S7 "PB1" SW_TL3301_J 2669.16,2178.94 r0 top
S8 "BSL" SW_TL1015AF160QG 551.3,1547.53 r180 top
SH1 "M50-2000005" FP-M50-2000005_CONN_SHUNT2-MFG 804.35,1828.64 r180 top
SH2 "M50-2000005" FP-M50-2000005_CONN_SHUNT2-MFG 804.35,1951.58 r180 top
SH-J1 "881545-2" TE_881545-2 1710.6,996.29 r0 top
SH-J2 "881545-2" TE_881545-2 1709.92,798.55 r0 top
SH-J3 "881545-2" TE_881545-2 1711.5,898.12 r0 top
SH-J4 "881545-2" TE_881545-2 1713.09,1198.44 r0 top
SH-J5 "881545-2" TE_881545-2 1710.14,1097.09 r0 top
SH-J6 "881545-2" TE_881545-2 1709.93,698.99 r0 top
SH-J7 "881545-2" TE_881545-2 1732.28,448.82 r270 top
SH-J8 "881545-2" TE_881545-2 1681.1,1488.19 r180 top
SH-J9 "881545-2" TE_881545-2 1428.15,1486.22 r180 top
TP1 "5126" Keystone5126 429.2,1153.93 r0 top
TP2 "5126" Keystone5126 3238,1833 r0 top
TP3 "5126" Keystone5126 3287.4,826.77 r0 top
TP4 "5013" Keystone5013 2042.31,1926.8 r0 top
TP5 "5013" Keystone5013 2048.41,1573.13 r270 top
TP6 "TP_H0.45P0.75" TP_H045P075 2090,1476 r0 top
TP7 "TP_H0.45P0.75" TP_H045P075 2061,1420 r0 top
TP8 "TP_H0.45P0.75" TP_H045P075 1863.77,861.42 r90 top
TP9 "5011" Keystone5011 1189.4,1929.13 r90 top
TP10 "5011" Keystone5011 971.36,1929.13 r0 top
TP12 "5010" Keystone5010 2950.7,1858.42 r90 top
TP13 "5010" Keystone5010 2703.35,1858.42 r90 top
TP14 "TP_H0.45P0.75" TP_H045P075 1123.03,1662.4 r90 top
U1 "ULC1001RQTR" RQT0032A-MFG 2059.89,1259.86 r180 top
U2 "DRV2911QRGFRQ1" RGF0040F-MFG 2050.05,889.27 r90 top locked
U3 "LM5155QDSSRQ1" DSS0012C 1242.94,876.23 r90 top
U4 "SN74LVC1G04QDCKRQ1" DCK0005A_L 1123.43,1015.01 r90 top
U5 "LMR36503MSC3RPETQ1" RPE0009A 1320.8,266.39 r0 top
U6 "TLV365DBVR" DBV0005A-MFG 1830.67,1720.59 r270 top
U7 "MSP430F5510IRGZR" RGZ0048A 905.99,1420.04 r90 top
U8 "24FC512-I/MF" DFNS-MF8 1291.36,1191.49 r180 bottom locked
U9 "TPD4E004DRYR" DRY0006A 489.37,2126.72 r270 top
Y1 "LFSPXO071190REEL" FP-LFSPXO071190REEL_SMT_XTAL_2MM0_1MM6-MFG 2185.6,1464.01 r270 top
Y2 "ABM8-24.000MHZ-B2-T" XTAL_ABM8 538.5,1337.29 r180 top
ZZ1 "This Assembly Note is for PCB labels only" AssemblyNoteLabel 5398.71,2496.72 r0 top
ZZ2 "These assemblies are ESD sensitive, ESD precautions shall be observed." AssemblyNote 5398.71,2387.83 r0 top
ZZ3 "These assemblies must be clean and free from flux and all contaminants. Use of no clean flux is not acceptable." AssemblyNote 5398.71,2299.27 r0 top
ZZ4 "These assemblies must comply with workmanship standards IPC-A-610 Class 2, unless otherwise specified." AssemblyNote 5398.71,2210.72 r0 top
ZZ5 "Indication provided for the D* components at their cathode side." AssemblyNote 5398.72,2129.61 r0 top

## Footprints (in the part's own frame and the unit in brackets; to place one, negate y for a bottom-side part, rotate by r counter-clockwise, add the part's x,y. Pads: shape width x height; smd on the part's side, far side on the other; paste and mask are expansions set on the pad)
0201 [mm] "Data from Kemet datasheet CC101_COM dated 7/28/11"
  rect 0.46x0.42 smd mask+0.048: 1(-0.33,0) 2(0.33,0)
  body extent -0.31,-0.16 0.31,0.16, height 0.26
0201_033L [mm] "0201"
  rect 0.36x0.32 smd mask+0.048: 1(-0.28,0) 2(0.28,0)
  body extent -0.31,-0.16 0.31,0.16, height 0.33
0201L [mm] "Data from Kemet datasheet CC101_COM dated 7/28/11"
  rect 0.36x0.32 smd mask+0.048: 1(-0.28,0) 2(0.28,0)
  body extent -0.31,-0.16 0.31,0.16, height 0.26
0402 [mm] "0402 from SM-752 data"
  rect 0.8x0.6 smd: 1(-0.6,0) 2(0.6,0)
  silkscreen extent -1.22,-0.52 1.22,0.52, body extent -0.55,-0.3 0.55,0.3, height 0.6
0402L [mm] "0402 from SM-752 data"
  rect 0.6x0.5 smd: 1(-0.5,0) 2(0.5,0)
  body extent -0.55,-0.3 0.55,0.3, height 0.6
0402S [mil] "Based on C0402S footprint from PADS legacy"
  rect 15x24 smd: 1(-20,0) 2(20,0)
  body extent -22,-12 22,12, height 24
0603 [mm] "0603 from SM-752 data"
  rect 1x0.95 smd: 1(-0.8,0) 2(0.8,0)
  silkscreen extent -1.52,-0.69 1.52,0.69, body extent -0.87,-0.47 0.87,0.47, height 1
0603L [mm] "0603 from SM-752 data"
  rect 0.8x0.85 smd: 1(-0.7,0) 2(0.7,0)
  silkscreen extent -0.07,-0.33 0.07,0.33, body extent -0.87,-0.47 0.87,0.47, height 1
0603S [mil]
  rect 20x35 smd: 1(-30,0) 2(30,0)
  body extent -34,-19 34,19, height 39
0805_150 [mm] "0805 / 1.5 mm height"
  rect 1.15x1.45 smd: 1(-0.9,0) 2(0.9,0)
  silkscreen extent -0.1,-0.8 0.1,0.8, body extent -1.1,-0.72 1.1,0.72, height 1.5
0805L [mm] "0805 from SM-752 data"
  rect 1.1x1.4 smd: 1(-0.75,0) 2(0.75,0)
  body extent -1.1,-0.72 1.1,0.72, height 1.45
1206_180 [mm] "1206_180"
  rect 1.1x1.6 smd: 1(-1.7,0) 2(1.7,0)
  silkscreen extent -0.9,-1 0.9,1, body extent -1.75,-0.95 1.75,0.95, height 1.8
1206_180L [mm] "1206_180"
  rect 1.1x1.75 smd: 1(-1.35,0) 2(1.35,0)
  silkscreen extent -0.4,-0.77 0.4,0.77, body extent -1.75,-0.95 1.75,0.95, height 1.8
1210_270L [mm] "1210"
  rect 1.1x2.6 smd: 1(-1.35,0) 2(1.35,0)
  silkscreen extent -0.4,-1.2 0.4,1.2, body extent -1.7,-1.35 1.7,1.35, height 2.7
1210_280 [mm] "SMD, 2-Leads, Body 3.6x2.8mm, Height 2.8mm"
  rect 1.1x2.2 smd: 1(-1.65,0) 2(1.65,0)
  silkscreen extent -0.84,-1.4 0.84,1.4, body extent -1.8,-1.4 1.8,1.4, height 2.8
2512 [mm] "Chip Resistor, Body 6.3x3.2mm, IPC Medium Density"
  rect 1.3x3.4 smd: 1(-2.95,0) 2(2.95,0)
  silkscreen extent -1.9,-1.6 1.9,1.6, body extent -3.22,-1.67 3.22,1.67, height 0.71
AssemblyNote [mil] "Assembly Note"
AssemblyNoteLabel [mil] "Assembly Note for PCB Labels"
Bourns_3352T [mm] "TH, 3-Leads, Body 9.53x8.89mm, Pitch 2.54mm"
  rect 1.35x1.35 hole 0.85: 1(-2.54,0)
  round 1.35 hole 0.85: 2(0,0) 3(2.54,0)
  silkscreen extent -4.44,-2.6 4.44,7.31, body extent -4.44,-2.21 4.45,7.32, height 3.81
CONN_PEC03SAAN [mm] "SULLINS"
  rect 1.5x1.5 hole 1.016: 1(-2.54,0)
  round 1.5 hole 1.016: 2(0,0) 3(2.54,0)
  silkscreen extent -4.72,-1.27 3.81,1.27, body extent -3.84,-1.3 3.84,1.3, height 8.38
CONN_PEC06DAAN [mm] "SULLINS"
  rect 1.65x1.65 hole 1.016 mask+0: 1(-6.35,-1.27)
  round 1.65 hole 1.016 mask+0: 2(-6.35,1.27) 3(-3.81,-1.27) 4(-3.81,1.27) 5(-1.27,-1.27) 6(-1.27,1.27) 7(1.27,-1.27) 8(1.27,1.27) 9(3.81,-1.27) 10(3.81,1.27) 11(6.35,-1.27) 12(6.35,1.27)
  silkscreen extent -8.72,-2.6 7.62,2.54, body extent -7.62,-2.54 7.62,2.54, height 8.38
CONN_RAPC712X [mm] "Conn_DC Jack"
  oval 1.7x4.3 hole 1.01 slot 3.56 at 90 deg: 1(-13.741,0)
  oval 1.5x3.8 hole 0.76 slot 3.05 at 90 deg: 2(-7.493,0)
  oval 3.8x1.5 hole 0.76 slot 3.05 at 0 deg: 3(-10.744,4.7)
  silkscreen extent -14.48,-4.57 0.25,4.57, body extent -14.5,-4.57 0.23,4.83, height 11.18
CRE2512-R5_R9 [mm] "SMD, 2-Leads, Body 6.45x3.35mm, Pitch 6.2mm"
  rect 2.1x4 smd: 1(-3.1,0) 2(3.1,0)
  silkscreen extent -1.6,-1.78 1.6,1.78, body extent -3.32,-1.77 3.32,1.77, height 0.9
DBV0005A-MFG [mm]
  rrect17% 1.1x0.6 smd paste+0 mask+0: 1(-1.3,0.95) 2(-1.3,0) 3(-1.3,-0.95) 4(1.3,-0.95) 5(1.3,0.95)
  silkscreen extent -2.52,-1.52 0.87,1.53, body extent -1.95,-1.78 1.95,1.78, height 0.25
DCK0005A_L [mm] "SOT353, 5-Leads, Body 2x1.3mm, Pitch 0.65mm, Lead Span 2.1mm, IPC High Density"
  rrect25% 0.65x0.4 smd: 1(-1.025,0.65) 2(-1.025,0) 3(-1.025,-0.65) 4(1.025,-0.65) 5(1.025,0.65)
  silkscreen extent -1.27,-1.09 0.56,1.09, body extent -1.14,-1 1.14,1, height 0.95
DFNS-MF8 [mm] "SON, 8-Leads, Body 5x6mm, Pitch 1.27mm, Microchip Recommended"
  oval 1.1x0.45 smd: 1(-2.8,1.905) 2(-2.8,0.635) 3(-2.8,-0.635) 4(-2.8,-1.905) 5(2.8,-1.905) 6(2.8,-0.635) 7(2.8,0.635) 8(2.8,1.905)
  rect 2.4x4.1 smd: 9(0,0)
  silkscreen extent -3.81,-2.7 3.2,2.79, body extent -3.05,-2.55 3.05,2.55, height 1.02
DRY0006A [mm] "USON-6"
  rrect67% 0.45x0.3 smd paste-0.05 mask-0.05: 1(-0.275,0.5)
  rrect67% 0.4x0.3 smd paste-0.05 mask-0.05: 2(-0.3,0) 3(-0.3,-0.5) 4(0.3,-0.5) 5(0.3,0) 6(0.3,0.5)
  body extent -0.5,-0.72 0.5,0.72, height 0.58
DSS0012C [mm] "WSON-12"
  rrect40% 0.5x0.25 smd: 1(-0.95,1.25) 2(-0.95,0.75) 3(-0.95,0.25) 4(-0.95,-0.25) 5(-0.95,-0.75) 6(-0.95,-1.25) 7(0.95,-1.25) 8(0.95,-0.75) 9(0.95,-0.25) 10(0.95,0.25) 11(0.95,0.75) 12(0.95,1.25)
  rrect11% 0.95x1.17 on Top Paste: 13(0,0.685) 13(0,-0.685)
  rrect11% 1x2.65 smd paste-0.5: 13(0,0)
  body extent -1,-1.5 1,1.5, height 0.81
Fiducial10-20 [mm]
  round 1 smd mask+0.5: 1(0,0)
  Top Layer keep-out circle w1.178: c0,0 r0.5
FP-0475901001_CONN_USB_7MM50_5MM90-MFG [mm]
  rrect25% 0.4x1.35 smd paste+0 mask+0: 1(1.3,2.475) 2(0.65,2.475) 3(0,2.475) 4(-0.65,2.475) 5(-1.3,2.475)
  rrect100% 1.05x1.25 hole 0.65 slot 0.85 at 90 deg paste-2539.97 mask+0: 6(-2.225,2.8) 7(2.225,2.8)
  rrect100% 1.2x1.9 hole 0.8 slot 1.5 at 90 deg paste-2539.97 mask+0: 8(-4.075,-0.2) 10(4.075,-0.2)
  round 1.238 smd paste-1000 mask+0: 8(-3.988,-0.2) 10(3.988,-0.2)
  round 1.238 smd far side paste-1000 mask+0: 8(-3.988,-0.2) 10(3.988,-0.2)
  rrect5% 2.9x1.9 smd paste+0 mask+0: 9(0,-0.2)
  Top Layer region: 3.3,0.75 4.075,0.75 4.305,0.704 4.499,0.574 4.629,0.38 4.675,0.15 4.675,0.15 4.675,-0.55 4.629,-0.78 4.499,-0.974 4.305,-1.104 4.075,-1.15 4.075,-1.15 3.3,-1.15
  Top Layer region: -3.3,0.75 -4.075,0.75 -4.305,0.704 -4.499,0.574 -4.629,0.38 -4.675,0.15 -4.675,0.15 -4.675,-0.55 -4.629,-0.78 -4.499,-0.974 -4.305,-1.104 -4.075,-1.15 -4.075,-1.15 -3.3,-1.15
  Bottom Layer region: 3.3,0.75 4.075,0.75 4.305,0.704 4.499,0.574 4.629,0.38 4.675,0.15 4.675,0.15 4.675,-0.55 4.629,-0.78 4.499,-0.974 4.305,-1.104 4.075,-1.15 4.075,-1.15 3.3,-1.15
  Bottom Layer region: -3.3,-1.15 -4.075,-1.15 -4.305,-1.104 -4.499,-0.974 -4.629,-0.78 -4.675,-0.55 -4.675,-0.55 -4.675,0.15 -4.629,0.38 -4.499,0.574 -4.305,0.704 -4.075,0.75 -4.075,0.75 -3.3,0.75
  silkscreen extent -4.1,1.13 4.1,3.92, body extent -4.78,-3.25 4.78,3.52, height 0.25
FP-C0805C472KBRACAUTO_0805-MFG [mm]
  rrect11% 0.95x1.35 smd paste+0 mask+0: 1(-0.75,0) 2(0.75,0)
  silkscreen extent -1.1,-1.05 1.1,1.05, body extent -1,-0.63 1,0.63, height 1.4
FP-C0805C822JAGACAUTO_0805-MFG [mm]
  rrect11% 0.95x1.35 smd paste+0 mask+0: 1(-0.75,0) 2(0.75,0)
  silkscreen extent -1.1,-1.07 1.1,1.07, body extent -1,-0.63 1,0.63, height 0.88
FP-CGA2B1X7R1A154M050BC_0402-MFG [mm]
  rrect25% 0.4x0.5 smd paste+0 mask+0: 1(-0.4,0) 2(0.4,0)
  silkscreen extent -0.53,-0.63 0.53,0.63, body extent -0.5,-0.25 0.5,0.25, height 0.55
FP-ERJ-1GNF2261C_0201-MFG [mm]
  rrect40% 0.25x0.3 smd paste+0 mask+0: 1(-0.3,0) 2(0.3,0)
  silkscreen extent -0.32,-0.54 0.31,0.54, body extent -0.3,-0.15 0.3,0.15, height 0.26
FP-ERJ-H3G0R00V_0603-MFG [mm]
  rrect15% 0.65x0.9 smd paste+0 mask+0: 1(-0.725,0) 2(0.725,0)
  silkscreen extent 0,-0.48 0,0.48, body extent -0.8,-0.4 0.8,0.4, height 0.55
FP-HCJ0201ZT0R00_0201-MFG [mm]
  rrect33% 0.3x0.35 smd paste+0 mask+0: 1(-0.275,0) 2(0.275,0)
  silkscreen extent -0.43,-0.55 0.43,0.55, body extent -0.53,-0.28 0.53,0.28, height 0.25
FP-LFSPXO071190REEL_SMT_XTAL_2MM0_1MM6-MFG [mm]
  rrect13% 0.88x0.78 smd paste+0 mask+0: 1(-0.64,-0.49) 2(0.64,-0.49) 3(0.64,0.49) 4(-0.64,0.49)
  silkscreen extent -1.77,-1.3 1,1.3, body extent -1,-0.8 1,0.8, height 0.8
FP-LMF105B7473KVHF_0402-MFG [mm]
  rrect22% 0.45x0.5 smd paste+0 mask+0: 1(-0.475,0) 2(0.475,0)
  silkscreen extent -0.53,-0.63 0.53,0.63, body extent -0.5,-0.25 0.5,0.25, height 0.55
FP-M50-2000005_CONN_SHUNT2-MFG [mil]
  body extent -56,-31 56,31, height 10
FP-M50-3530242_HDR2-MFG [mm]
  rrect9% 1.1x1.1 hole 0.6 paste-2539.97 mask+0: 1(-0.635,0)
  round 1.1 hole 0.6 paste-2539.97 mask+0: 2(0.635,0)
  silkscreen extent -1.6,-1.7 1.6,1.1, body extent -1.62,-1.2 1.62,1.2, height 0.25
FP-RK73H1JTTD3481F_0603-MFG [mm]
  rrect20% 0.5x0.6 smd paste+0 mask+0: 1(-0.75,0) 2(0.75,0)
  silkscreen extent -0.13,-0.45 0.13,0.45, body extent -1.1,-0.55 1.1,0.55, height 0.25
FP-RT0402BRD076K34L_0402-MFG [mm]
  rrect20% 0.5x0.6 smd paste+0 mask+0: 1(-0.5,0) 2(0.5,0)
  silkscreen extent -0.5,-0.71 0.5,0.7, body extent -0.85,-0.4 0.85,0.4, height 0.25
FP-SRP7050TA-220M_SMT2_7MM3_6MM6-MFG [mm]
  rrect3% 2.95x3.5 smd paste+0 mask+0: 1(-2.725,0) 2(2.725,0)
  silkscreen extent -3.5,-3.45 3.5,3.45, body extent -4.3,-3.55 4.3,3.55, height 0.25
FP-TNPW02012K00BEED_0201-MFG [mm]
  rrect36% 0.28x0.43 smd paste+0 mask+0: 1(-0.255,0) 2(0.255,0)
  silkscreen extent -0.3,-0.63 0.3,0.63, body extent -0.3,-0.15 0.3,0.15, height 0.27
FP-TNPW02016K04BEED_0201-MFG [mm]
  rrect36% 0.28x0.43 smd paste+0 mask+0: 1(-0.255,0) 2(0.255,0)
  silkscreen extent -0.3,-0.63 0.3,0.63, body extent -0.3,-0.15 0.3,0.15, height 0.27
FP-V30K45-01HM3-H_FlatPAK5x6-MFG [mm]
  rrect13% 0.75x1 smd paste+0 mask+0: 1(-1.905,-2.795) 2(-0.635,-2.795) 3(0.635,-2.795) 4(1.905,-2.795)
  round 3.812 smd paste+0 mask+0: 5-6-7-8(-0.052,0.573)
  Top Layer region: 2.775,-1.545 -2.775,-1.545 -2.775,-0.145 -2.28,-0.145 -2.28,3.295 -1.53,3.295 -1.53,2.735 -0.95,2.735 -0.95,3.295 -0.2,3.295 -0.2,2.735 0.2,2.735 0.2,3.295 0.95,3.295 0.95,2.735 1.53,2.735 1.53,3.295 2.28,3.295 2.28,0.145 2.775,0.145 2.775,1.545
  silkscreen extent -3.15,-4.07 3.15,3, body extent -2.58,-3.1 2.58,3.1, height 1.09
FP-VMP-1R00-1.0-U_2010-MFG [mm]
  rrect8% 1.25x3 smd paste+0 mask+0: 1(-2.375,0) 2(2.375,0)
  silkscreen extent -1.38,-1.37 1.38,1.37, body extent -2.54,-1.27 2.54,1.27, height 0.55
IEC_HighVoltage_Small [mil]
  silkscreen extent -107,-88 107,97
Keystone5010 [mil] "Keystone Multipurpose loops"
  round 87 hole 63: 1(0,0)
  silkscreen extent -70,-70 70,70, body extent -63,-63 63,62, height 319
Keystone5011 [mil] "Keystone Multipurpose loops"
  round 87 hole 63: 1(0,0)
  silkscreen extent -70,-70 70,70, body extent -63,-63 63,62, height 319
Keystone5013 [mil] "Keystone Multipurpose loops"
  round 87 hole 63: 1(0,0)
  silkscreen extent -70,-70 70,70, body extent -63,-63 63,62, height 319
Keystone5126 [mil] "Keystone Multipurpose loops"
  round 87 hole 63: 1(0,0)
  silkscreen extent -70,-70 70,70, body extent -63,-63 63,62, height 319
Keystone_1902C [mil] "Hex Standoff, 4-40 threaded, nylon"
  round 1 on Mech4: 0(0,0)
  body extent -145,-126 146,126, height 501
Label_650x200 [mil] "Thermal Transfer Label"
  round 1 on Mech13: 0(0,0)
  silkscreen extent -325,-100 325,100, body extent -325,-100 325,100, height 1
LED_LTST-C170_Red [mm] "LITE-ON"
  rect 1.2x1.2 smd: 1(-1.05,0) 2(1.05,0)
  silkscreen extent -1.6,-1 2.2,1, body extent -1.05,-0.67 1.05,0.67, height 1.1
LED_LTST-C171 [mm] "LITE-ON"
  rect 1.2x1.2 smd: 1(-1.05,0) 2(1.05,0)
  silkscreen extent -1.6,-1 2.2,1, body extent -1.05,-0.67 1.05,0.67, height 0.8
LTST-C193_Blue [mm] "SMD, 2-Leads, Body1.6x0.8mm"
  rect 0.8x0.8 smd: 1(-0.75,0) 2(0.75,0)
  silkscreen extent -1.2,-0.9 1.85,0.9, body extent -0.85,-0.45 0.85,0.45, height 0.45
LTST-C193_Green [mm] "SMD, 2-Leads, Body1.6x0.8mm"
  rect 0.8x0.8 smd: 1(-0.75,0) 2(0.75,0)
  silkscreen extent -1.2,-0.9 1.85,0.9, body extent -0.85,-0.45 0.85,0.45, height 0.45
Molex_039544-3002 [mm] "Terminal Block, 5.08mm, 2x1, TH"
  rect 2.15x2.15 hole 1.65: 1(-2.54,0)
  round 2.15 hole 1.65: 2(2.54,0)
  silkscreen extent -5.5,-4.8 5.08,5.11, body extent -5.08,-4.8 5.08,5.11, height 14.48
"NY PMS 440 0025 PH" [mm] "4-40 nylon screw and mounting hole"
  round 8 hole 3.2: 1(0,0)
  body extent -3.3,-3.3 3.3,3.3, height 2.69
OMRON_XG4C-1031 [mm] "TH, 10-Leads, Body 8.5x20mm, Pitch 2.54mm"
  rect 1.3x1.3 / inner round 1.4 / far side rect 1.4x1.4 hole 0.9: 1(-1.27,5.08)
  round 1.3 / inner round 1.4 / far side round 1.4 hole 0.9: 2(1.27,5.08) 3(-1.27,2.54) 4(1.27,2.54) 5(-1.27,0) 6(1.27,0) 7(-1.27,-2.54) 8(1.27,-2.54) 9(-1.27,-5.08) 10(1.27,-5.08)
  silkscreen extent -4.57,-10 4.4,10, body extent -4.1,-10 4.4,10, height 9.02
RGF0040F-MFG [mm]
  rrect40% 0.6x0.25 smd paste+0 mask+0: 1(-2.4,2.75) 2(-2.4,2.25) 3(-2.4,1.75) 4(-2.4,1.25) 5(-2.4,0.75) 6(-2.4,0.25) 7(-2.4,-0.25) 8(-2.4,-0.75) 9(-2.4,-1.25) 10(-2.4,-1.75) 11(-2.4,-2.25) 12(-2.4,-2.75) 21(2.4,-2.75) 22(2.4,-2.25) 23(2.4,-1.75) 24(2.4,-1.25) 25(2.4,-0.75) 26(2.4,-0.25) 27(2.4,0.25) 28(2.4,0.75) 29(2.4,1.25) 30(2.4,1.75) 31(2.4,2.25) 32(2.4,2.75)
  rrect40% 0.25x0.6 smd paste+0 mask+0: 13(-1.75,-3.4) 14(-1.25,-3.4) 15(-0.75,-3.4) 16(-0.25,-3.4) 17(0.25,-3.4) 18(0.75,-3.4) 19(1.25,-3.4) 20(1.75,-3.4) 33(1.75,3.4) 34(1.25,3.4) 35(0.75,3.4) 36(0.25,3.4) 37(-0.25,3.4) 38(-0.75,3.4) 39(-1.25,3.4) 40(-1.75,3.4)
  rrect3% 3.7x5.7 smd paste-1000 mask+0: 41(0,0)
  silkscreen extent -3.37,-3.55 2.55,3.55, body extent -2.8,-3.8 2.8,3.8, height 0.25
RGZ0048A [mm] "VQFN-48"
  rrect42% 0.6x0.24 smd: 1(-3.4,2.75) 2(-3.4,2.25) 3(-3.4,1.75) 4(-3.4,1.25) 5(-3.4,0.75) 6(-3.4,0.25) 7(-3.4,-0.25) 8(-3.4,-0.75) 9(-3.4,-1.25) 10(-3.4,-1.75) 11(-3.4,-2.25) 12(-3.4,-2.75) 25(3.4,-2.75) 26(3.4,-2.25) 27(3.4,-1.75) 28(3.4,-1.25) 29(3.4,-0.75) 30(3.4,-0.25) 31(3.4,0.25) 32(3.4,0.75) 33(3.4,1.25) 34(3.4,1.75) 35(3.4,2.25) 36(3.4,2.75)
  rrect42% 0.24x0.6 smd: 13(-2.75,-3.4) 14(-2.25,-3.4) 15(-1.75,-3.4) 16(-1.25,-3.4) 17(-0.75,-3.4) 18(-0.25,-3.4) 19(0.25,-3.4) 20(0.75,-3.4) 21(1.25,-3.4) 22(1.75,-3.4) 23(2.25,-3.4) 24(2.75,-3.4) 37(2.75,3.4) 38(2.25,3.4) 39(1.75,3.4) 40(1.25,3.4) 41(0.75,3.4) 42(0.25,3.4) 43(-0.25,3.4) 44(-0.75,3.4) 45(-1.25,3.4) 46(-1.75,3.4) 47(-2.25,3.4) 48(-2.75,3.4)
  rrect2% 5.15x5.15 smd paste-2.6: 49(0,0)
  body extent -3.5,-3.5 3.5,3.5, height 1
RPE0009A [mm] "VQFN, 9-Leads, Body 2x2.mm"
  rrect50% 0.2x0.2 smd paste+0: 1(-0.9,0.738) 4(-0.9,-0.738) 5(0.9,-0.738) 8(0.9,0.738)
  rrect40% 0.6x0.25 smd: 2(-0.9,0.25) 3(-0.9,-0.25) 6(0.9,-0.25) 7(0.9,0.25)
  rrect29% 0.35x1.3 smd paste-0.35: 9(0,0.55)
  Top Layer region: 1.2,-0.676 1.2,-0.801 1.196,-0.82 1.185,-0.836 1.169,-0.847 1.15,-0.851 1.15,-0.851 0.9,-0.851 0.881,-0.854 0.865,-0.865 0.854,-0.881 0.85,-0.901 0.85,-0.901 0.85,-1.151 0.846,-1.17 0.835,-1.186 0.819,-1.197 0.8,-1.201 0.8,-1.201 0.5,-1.201 0.481,-1.197 0.465,-1.186 0.454,-1.17 0.45,-1.151 0.45,-1.151 0.45,-0.676 0.454,-0.656 0.465,-0.64 0.481,-0.629 0.5,-0.626 0.5,-0.626 1.15,-0.626 1.169,-0.629 1.185,-0.64 1.196,-0.656 1.2,-0.676
  Top Layer region: -1.2,-0.676 -1.2,-0.801 -1.196,-0.82 -1.185,-0.836 -1.169,-0.847 -1.15,-0.851 -1.15,-0.851 -0.9,-0.851 -0.881,-0.854 -0.865,-0.865 -0.854,-0.881 -0.85,-0.901 -0.85,-0.901 -0.85,-1.151 -0.846,-1.17 -0.835,-1.186 -0.819,-1.197 -0.8,-1.201 -0.8,-1.201 -0.5,-1.201 -0.481,-1.197 -0.465,-1.186 -0.454,-1.17 -0.45,-1.151 -0.45,-1.151 -0.45,-0.676 -0.454,-0.656 -0.465,-0.64 -0.481,-0.629 -0.5,-0.626 -0.5,-0.626 -1.15,-0.626 -1.169,-0.629 -1.185,-0.64 -1.196,-0.656 -1.2,-0.676
  Top Layer region: 1.2,0.676 1.2,0.801 1.196,0.82 1.185,0.836 1.169,0.847 1.15,0.851 1.15,0.851 0.9,0.851 0.881,0.854 0.865,0.865 0.854,0.881 0.85,0.901 0.85,0.901 0.85,1.151 0.846,1.17 0.835,1.186 0.819,1.197 0.8,1.201 0.8,1.201 0.5,1.201 0.481,1.197 0.465,1.186 0.454,1.17 0.45,1.151 0.45,1.151 0.45,0.676 0.454,0.656 0.465,0.64 0.481,0.629 0.5,0.626 0.5,0.626 1.15,0.626 1.169,0.629 1.185,0.64 1.196,0.656 1.2,0.676
  Top Layer region: -1.2,0.676 -1.2,0.801 -1.196,0.82 -1.185,0.836 -1.169,0.847 -1.15,0.851 -1.15,0.851 -0.9,0.851 -0.881,0.854 -0.865,0.865 -0.854,0.881 -0.85,0.901 -0.85,0.901 -0.85,1.151 -0.846,1.17 -0.835,1.186 -0.819,1.197 -0.8,1.201 -0.8,1.201 -0.5,1.201 -0.481,1.197 -0.465,1.186 -0.454,1.17 -0.45,1.151 -0.45,1.151 -0.45,0.676 -0.454,0.656 -0.465,0.64 -0.481,0.629 -0.5,0.626 -0.5,0.626 -1.15,0.626 -1.169,0.629 -1.185,0.64 -1.196,0.656 -1.2,0.676
  body extent -1,-1 1,1, height 1
RQT0032A-MFG [mm]
  rrect25% 0.6x0.4 smd paste+0 mask+0: 1(-2.4,1.663) 8(-2.4,-1.637)
  rrect40% 0.65x0.25 smd paste+0 mask+0: 2(-2.375,1.138) 3(-2.375,0.688) 4(-2.375,0.238) 5(-2.375,-0.212) 6(-2.375,-0.662) 7(-2.375,-1.112)
  rrect40% 0.25x0.6 smd paste+0 mask+0: 9(-1.765,-2.15) 10(-1.315,-2.15)
  rrect40% 0.25x0.65 smd paste+0 mask+0: 11(-0.865,-2.125) 12(-0.415,-2.125) 13(0.035,-2.125) 29(-0.415,2.125) 32(-1.765,2.125)
  rrect40% 0.25x1.9 smd paste-1000 mask+0: 14(0.485,-1.5) 15(0.935,-1.5) 16(1.385,-1.5)
  round 0.389 smd paste-1000 mask+0: 17(2.116,-1.653)
  rrect40% 0.6x0.25 smd paste+0 mask+0: 18(2.4,-1.112) 19(2.4,-0.662) 20(2.4,-0.212) 22(2.4,0.688) 23(2.4,1.138)
  rrect40% 1.433x0.25 smd paste-1000 mask+0: 21(1.984,0.238)
  round 0.382 smd paste-1000 mask+0: 24(2.062,1.675)
  rrect40% 0.25x1.35 smd paste-1000 mask+0: 25(1.385,1.775)
  rrect40% 0.25x1.78 smd paste-1000 mask+0: 26(0.935,1.56)
  rrect40% 0.25x0.7 smd paste+0 mask+0: 27(0.485,2.1)
  rrect40% 0.25x1.15 smd paste-1000 mask+0: 28(0.035,1.875)
  rrect40% 0.25x0.625 smd paste+0 mask+0: 30(-0.865,2.137) 31(-1.315,2.137)
  Top Layer region: 1.85,2.4 1.854,2.419 1.865,2.435 1.881,2.446 1.9,2.45 1.9,2.45 2.2,2.45 2.225,2.443 2.243,2.425 2.25,2.4 2.25,2.4 2.25,1.863 2.65,1.863 2.675,1.856 2.693,1.838 2.7,1.813 2.7,1.813 2.7,1.513 2.693,1.488 2.675,1.47 2.65,1.463 2.65,1.463 1.9,1.463 1.881,1.467 1.865,1.478 1.854,1.494 1.85,1.513 1.85,1.513
  Top Layer region: 1.85,-2.4 1.85,-1.487 1.854,-1.468 1.865,-1.452 1.881,-1.441 1.9,-1.437 1.9,-1.437 2.65,-1.437 2.669,-1.441 2.685,-1.452 2.696,-1.468 2.7,-1.487 2.7,-1.487 2.7,-1.787 2.693,-1.812 2.675,-1.83 2.65,-1.837 2.65,-1.837 2.25,-1.837 2.25,-2.4 2.243,-2.425 2.225,-2.443 2.2,-2.45 2.2,-2.45 1.9,-2.45 1.875,-2.443 1.857,-2.425 1.85,-2.4
  silkscreen extent -3.58,-2.83 3.08,2.83, body extent -2.5,-2.25 2.5,2.25, height 1
Samtec_TSW-102-07-T-S [mm] "Header, 2.54 mm, 2x1, Tin, TH"
  rrect50% 1.55x1.55 hole 1.02: 1(-1.27,0)
  round 1.55 hole 1.02: 2(1.27,0)
  body extent -2.54,-1.27 2.54,1.27, height 8.38
SO-8FL [mm] "ON SEMICONDUCTOR, DFN5 5x6, 1.27P, CASE 488AA"
  rect 1x0.75 smd: 1(-2.795,1.905) 2(-2.795,0.635) 3(-2.795,-0.635) 4(-2.795,-1.905)
  rect 4.055x4.56 smd: 5(0.698,0)
  Top Layer region: -0.905,-2.775 -0.905,2.775 0,2.775 0,-2.775
  Top Layer region: 2.654,1.53 2.654,2.28 3.199,2.28 3.199,1.53
  Top Layer region: 2.649,-2.28 2.649,-1.53 3.199,-1.53 3.199,-2.28
  silkscreen extent -3.1,-2.6 3.1,2.9, body extent -3.17,-2.67 3.17,2.67, height 1.11
SOD-123 [mm] "On Semi recommended land pattern"
  rect 0.915x1.22 smd: 1(-1.637,0) 2(1.637,0)
  silkscreen extent -2.74,-1.17 2.03,1.17, body extent -1.93,-0.9 1.93,0.9, height 1.35
Sullins_GRPB031VWTC [mm] "Header, 1.27mm, 3x1, SMT"
  rect 0.76x2.25 smd: 1(-1.27,1.125) 2(0,-1.125) 3(1.27,1.125)
  silkscreen extent -2.1,-1.07 1.91,1.07, body extent -1.9,-1.75 1.91,1.75, height 5.1
SW_AYZ0102AGRLC [mm] "SMD, 3-Leads, Body 7.2x4mm, Pitch 2.5mm"
  rect 1x1.2 smd: 1(-2.5,2.6) 2(0,2.6) 3(2.5,2.6)
  round 0 hole 0.85 unplated paste-2539.97: MH1(-1.5,0)
  round 0 hole 0.85 unplated: MH2(1.5,0)
  silkscreen extent -3.6,-2.49 3.6,1.9, body extent -3.6,-2.49 3.6,2.8, height 1.5
SW_EVQ5PN04K [mm] "SMD, 2-Leads, Body 6x3.5mm"
  rrect6% 2x1.6 smd: 1(-2.7,0) 2(2.7,0)
  silkscreen extent -3,-1.75 3,1.75, body extent -3.6,-1.75 3.6,1.75, height 4.3
SW_SRB22A2FBBNN [mm] "TH, 2-Leads, Body 15.01x19mm"
  rect 1.7x5.7 hole 1.2 slot 5.2 at 90 deg: 1(-6.99,0)
  oval 1.7x5.7 hole 1.2 slot 5.2 at 90 deg: 2(0,0)
  silkscreen extent -10.9,-7.53 10.52,7.48, body extent -10.66,-7.51 10.66,7.51, height 17.73
SW_TL1015AF160QG [mm] "E-Switch"
  rrect11% 0.95x1.4 smd: 1(-2.075,0) 2(2.075,0)
  body extent -2.3,-1.5 2.3,1.5, height 2
SW_TL3301_J [mm] "SMD, 4-Leads, Body 6x6mm"
  rect 1.4x2.795 smd: 1(-2.25,2.413) 2(-2.25,-2.412) 3(2.25,2.413) 4(2.25,-2.412)
  silkscreen extent -3,-3 3,3.3, body extent -3,-3.3 3,3.3, height 5.3
TE_881545-2 [mil] "TE"
  round 1 on Mech3: 0(0,0)
  body extent -99,-49 99,49, height 530
TP_H045P075 [mm] "TP_H0.45P0.75"
  round 0.75 hole 0.45: 1(0,0)
XAL1010 [mm] "COILCRAFT"
  rect 2.38x11.31 smd: 1(-3.325,0) 2(3.325,0)
  silkscreen extent -5.3,-6 5.3,6, body extent -5.25,-5.9 5.25,5.9, height 10
XPL2010 [mm] "Coilcraft recommended land pattern Document 646-2 Revised 3/28/11"
  rect 1.04x2.2 smd: 1(-0.725,0) 2(0.725,0)
  silkscreen extent -1.52,-1.4 1.52,1.4, body extent -1.05,-1.1 1.05,1.1, height 1
XTAL_ABM8 [mm] "Abracon recommended land pattern"
  rect 1.05x1.3 smd: 1(-0.925,1.15) 2(-0.925,-1.15) 3(0.925,-1.15) 4(0.925,1.15)
  silkscreen extent -1.73,1.3 -1.2,2.07, body extent -1.35,-1.7 1.35,1.7, height 0.8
